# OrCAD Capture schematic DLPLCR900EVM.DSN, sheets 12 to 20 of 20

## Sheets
12 P09-Controller USB Osc Rst SSP: size A3
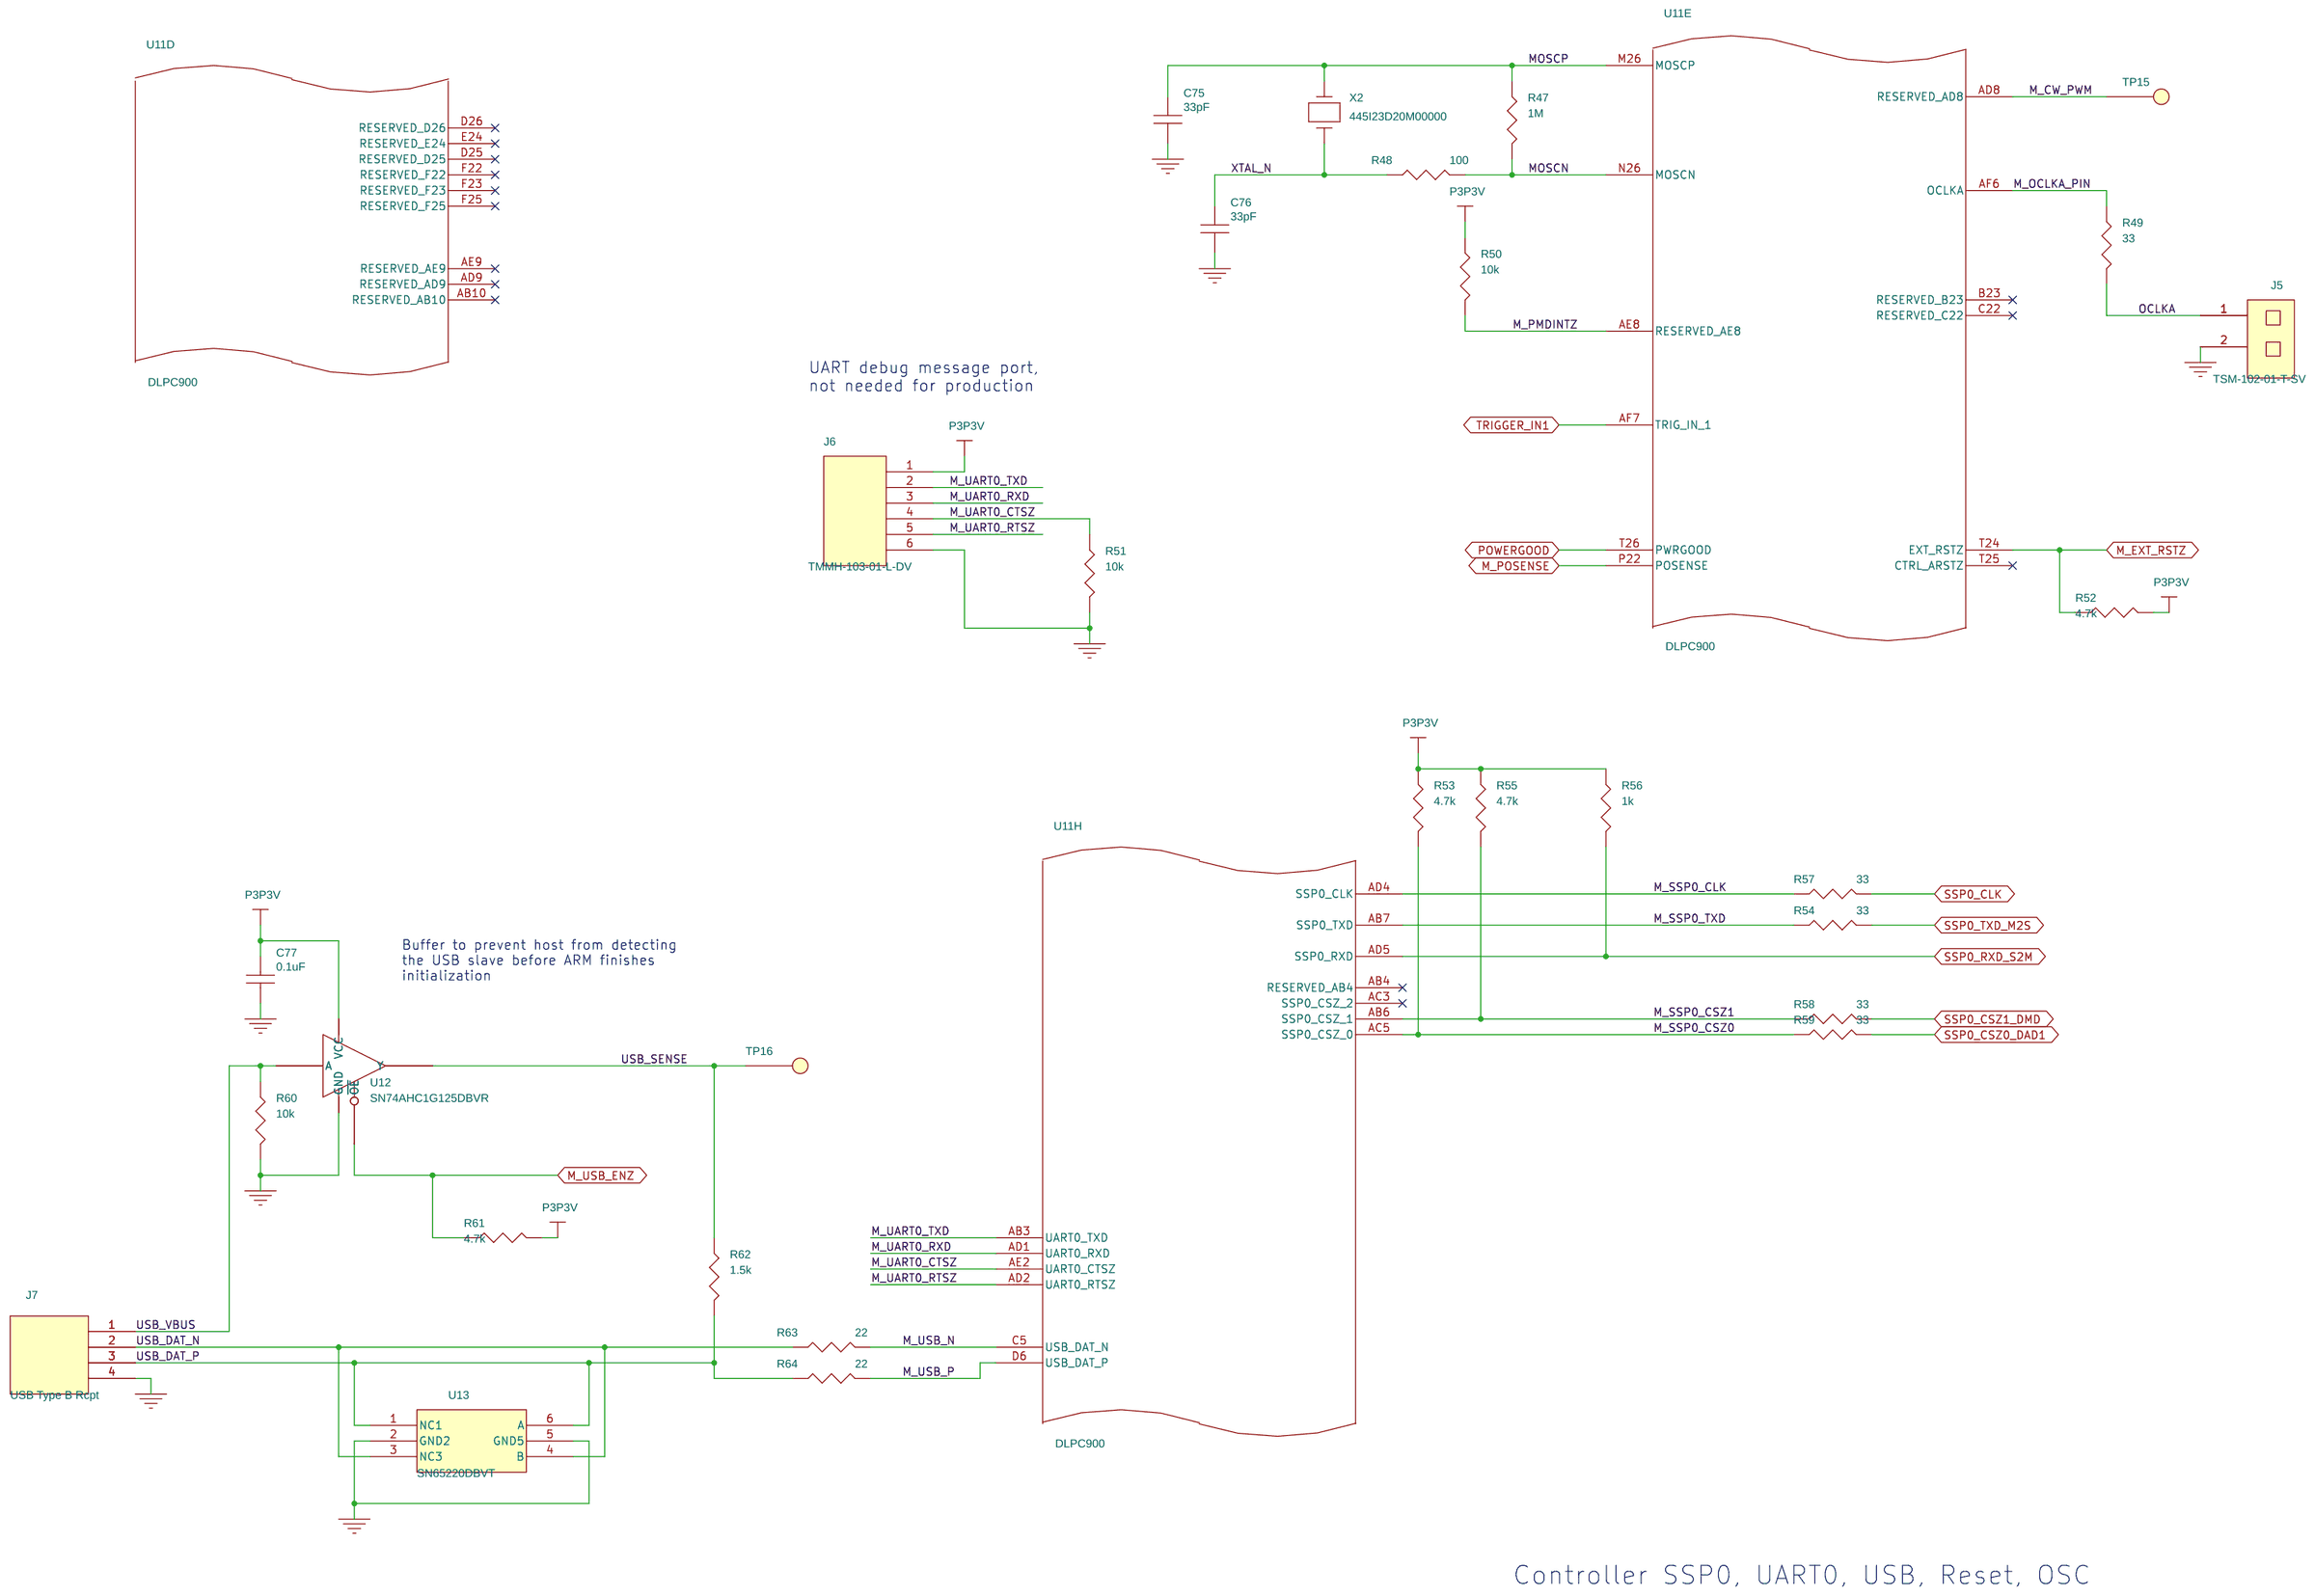
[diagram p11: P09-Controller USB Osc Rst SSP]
13 P08-Controller Vid DMD DAD io: size A3
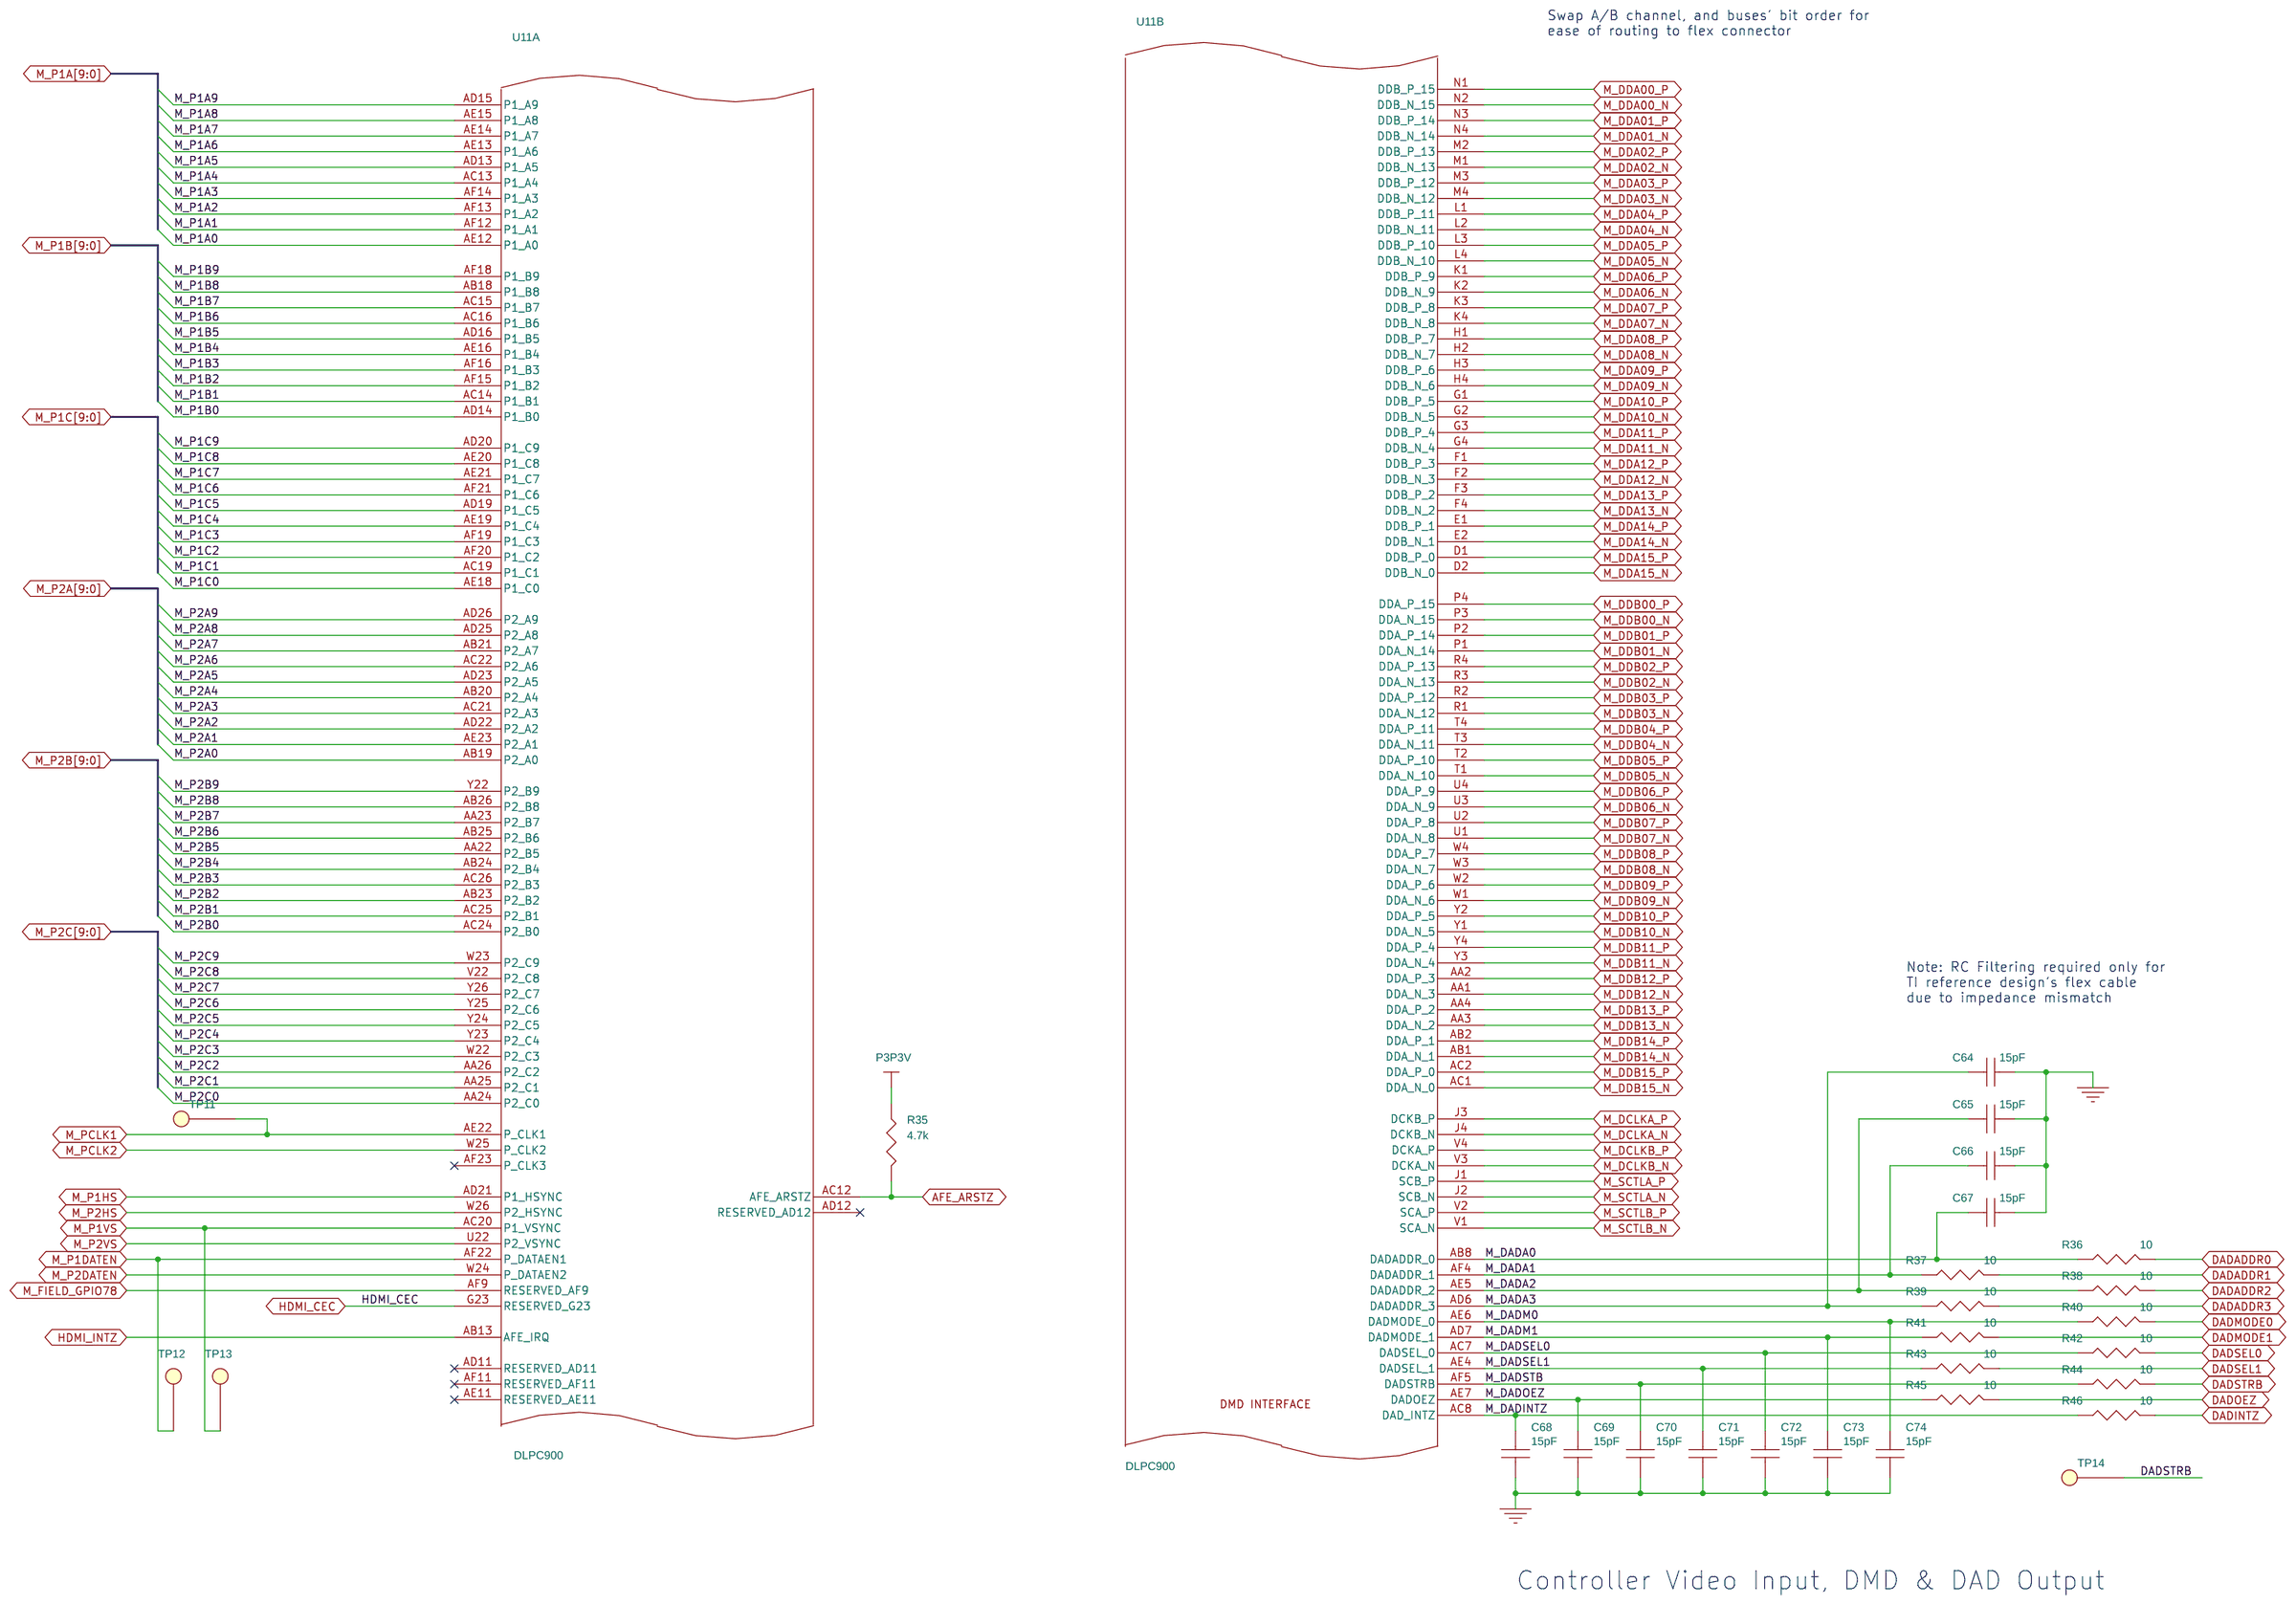
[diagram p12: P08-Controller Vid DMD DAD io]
14 P01-Title
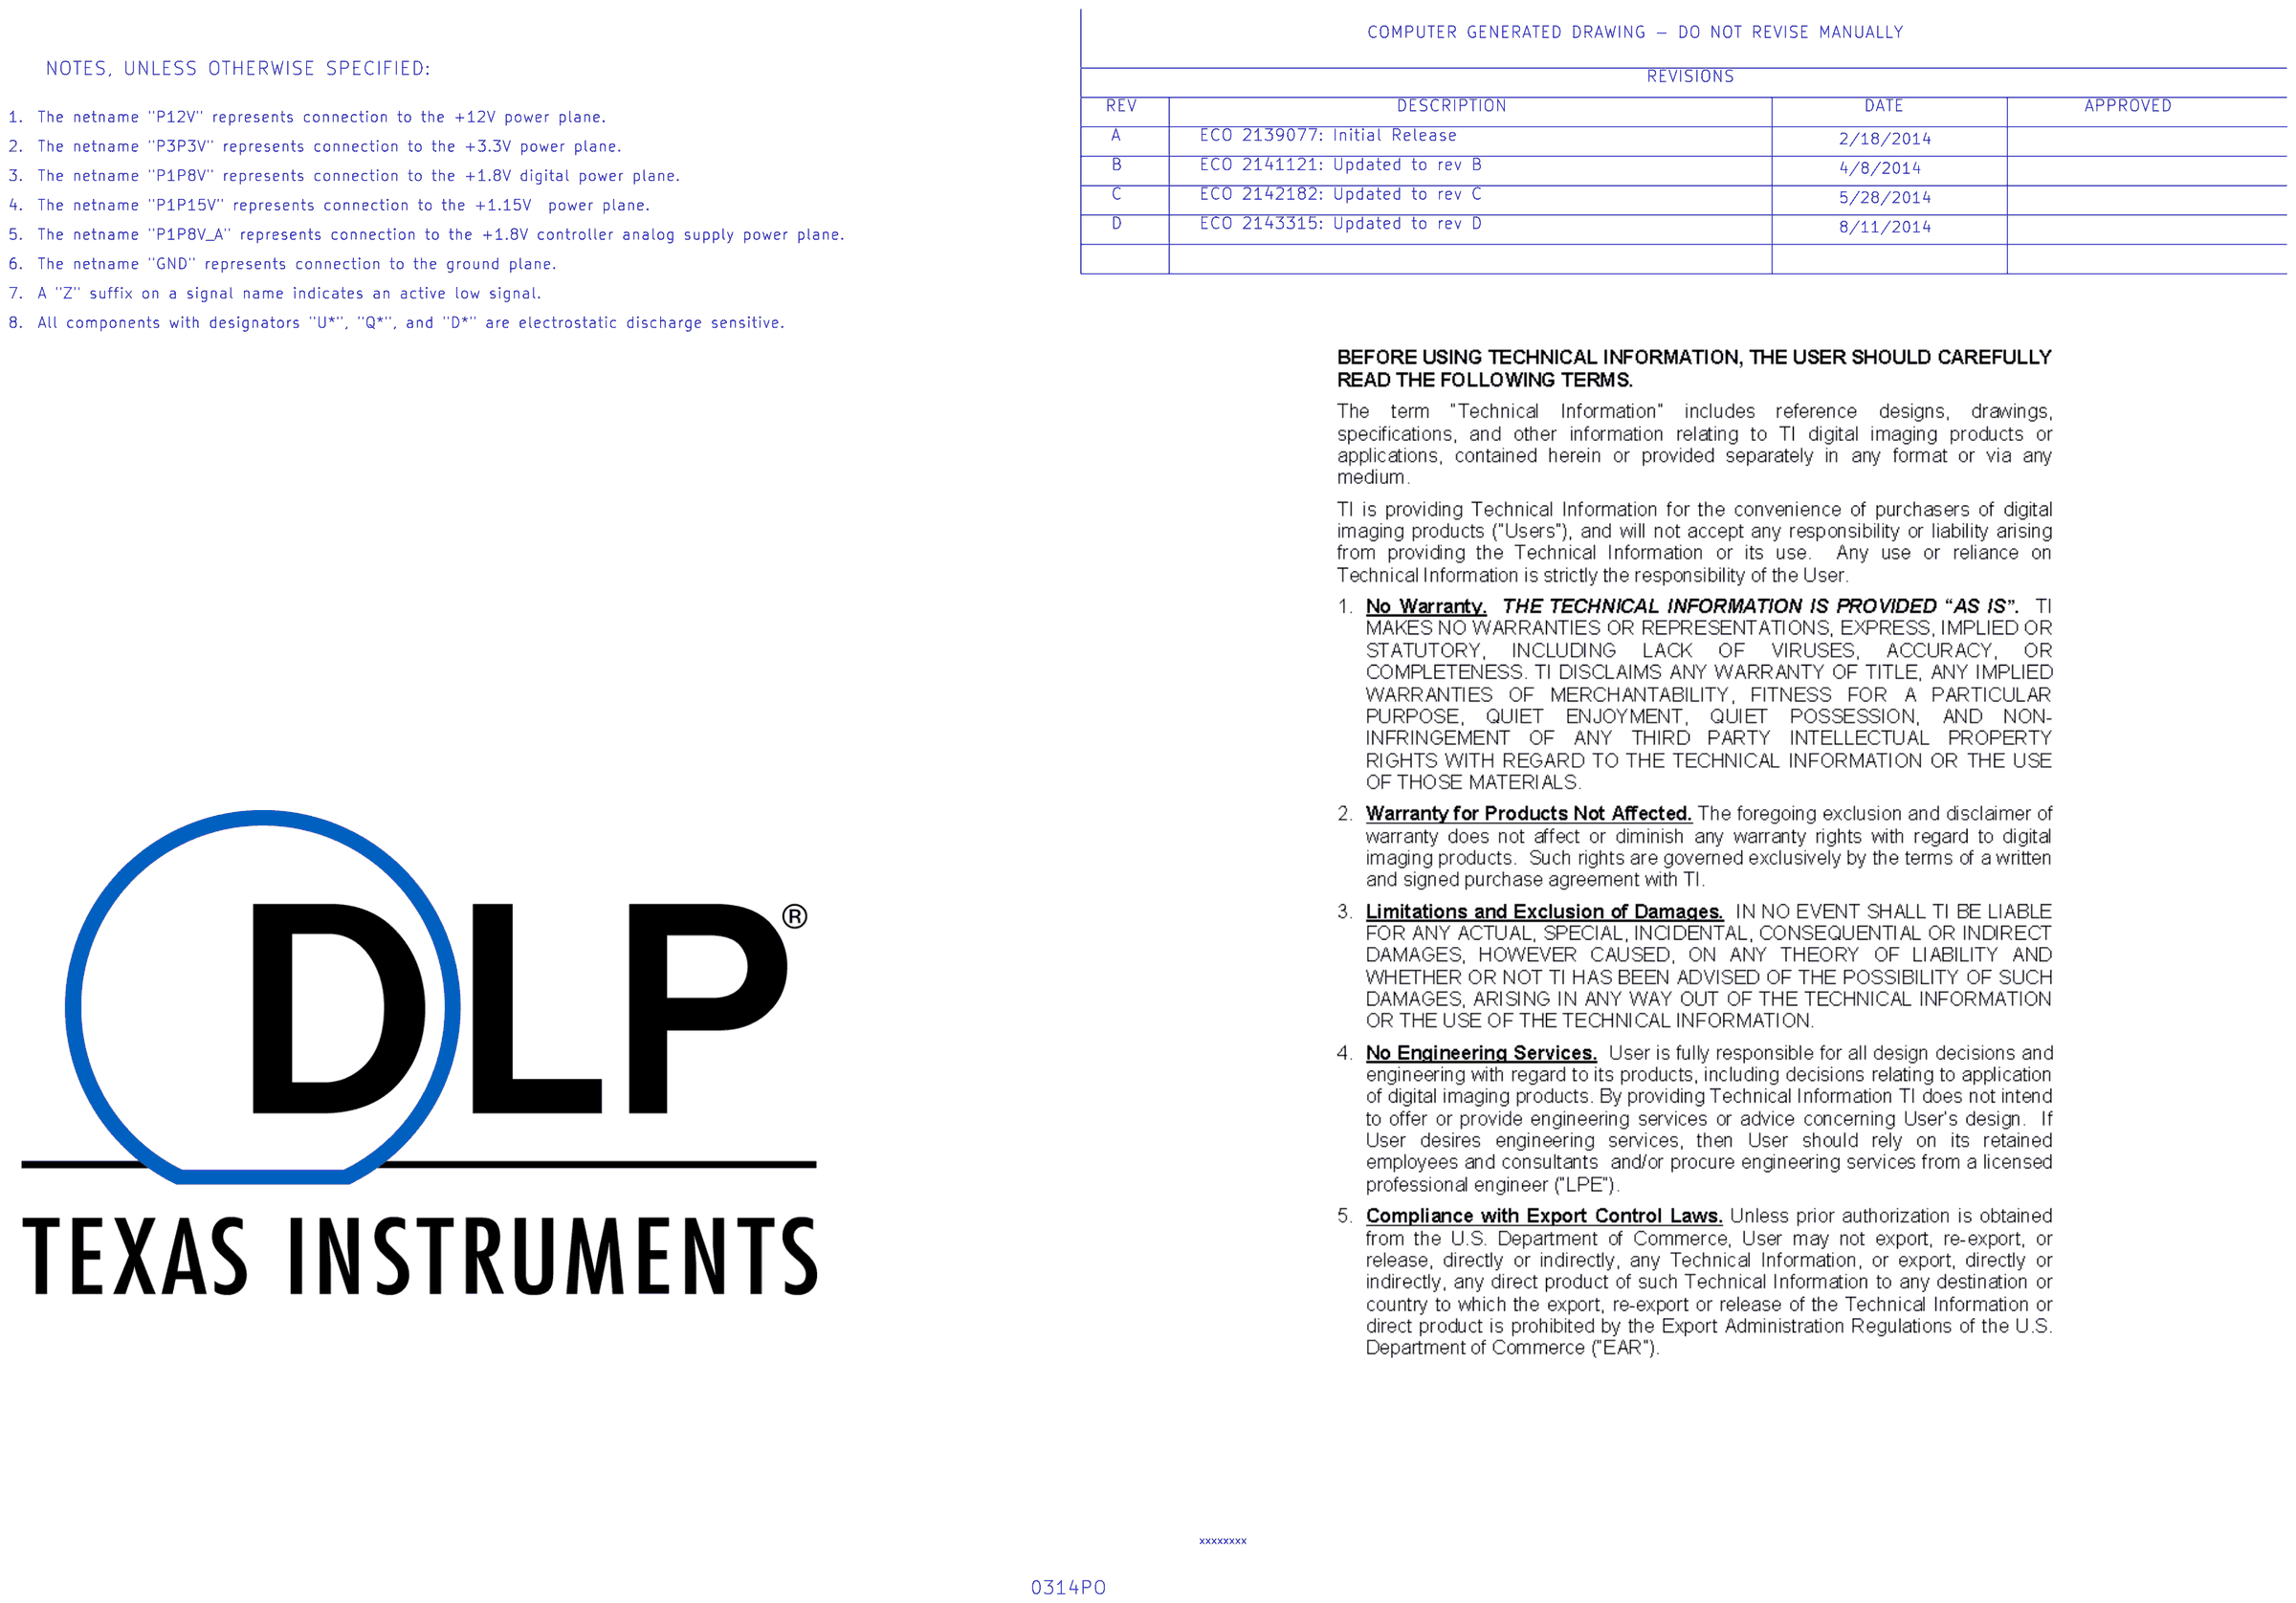
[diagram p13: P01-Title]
15 P03-Table Of Contents
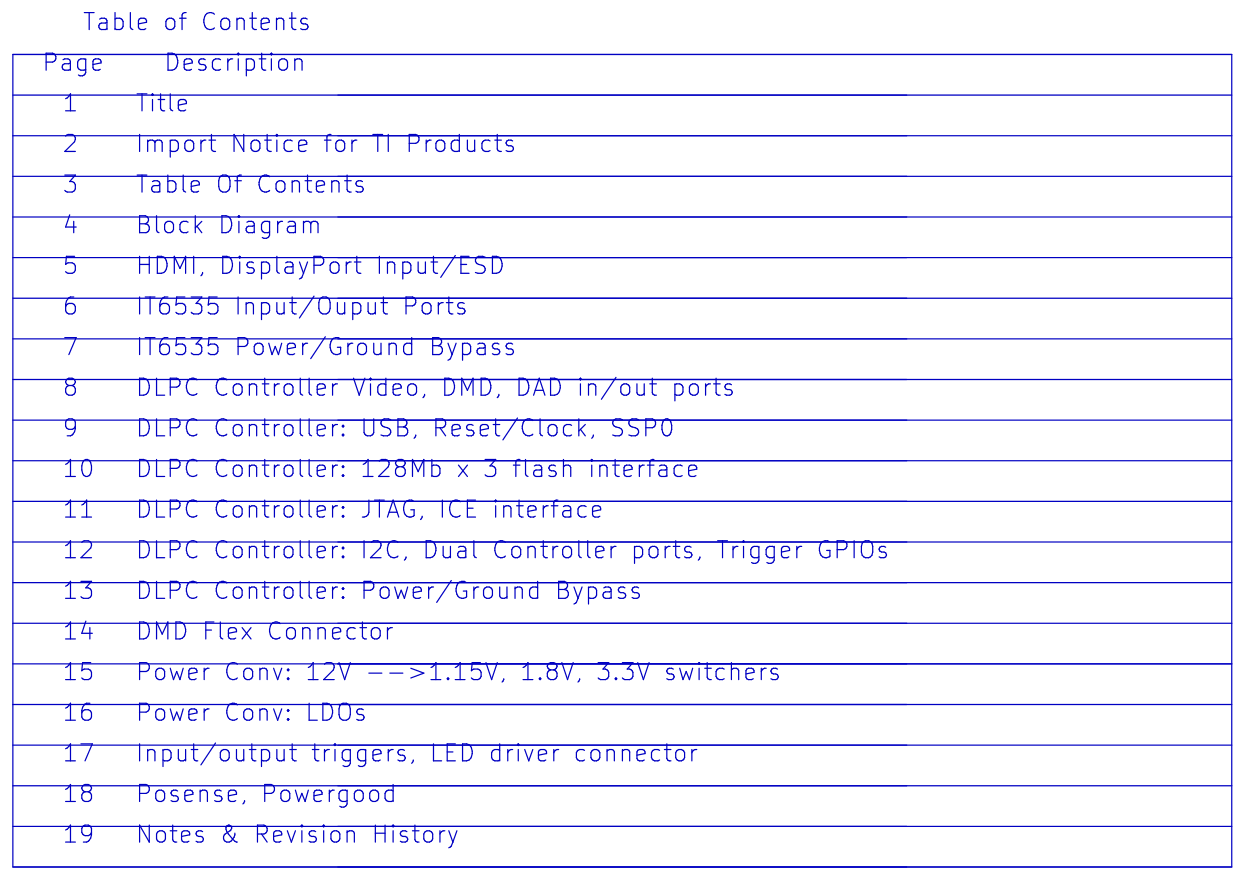
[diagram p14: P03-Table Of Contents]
16 P04-Block Diagram
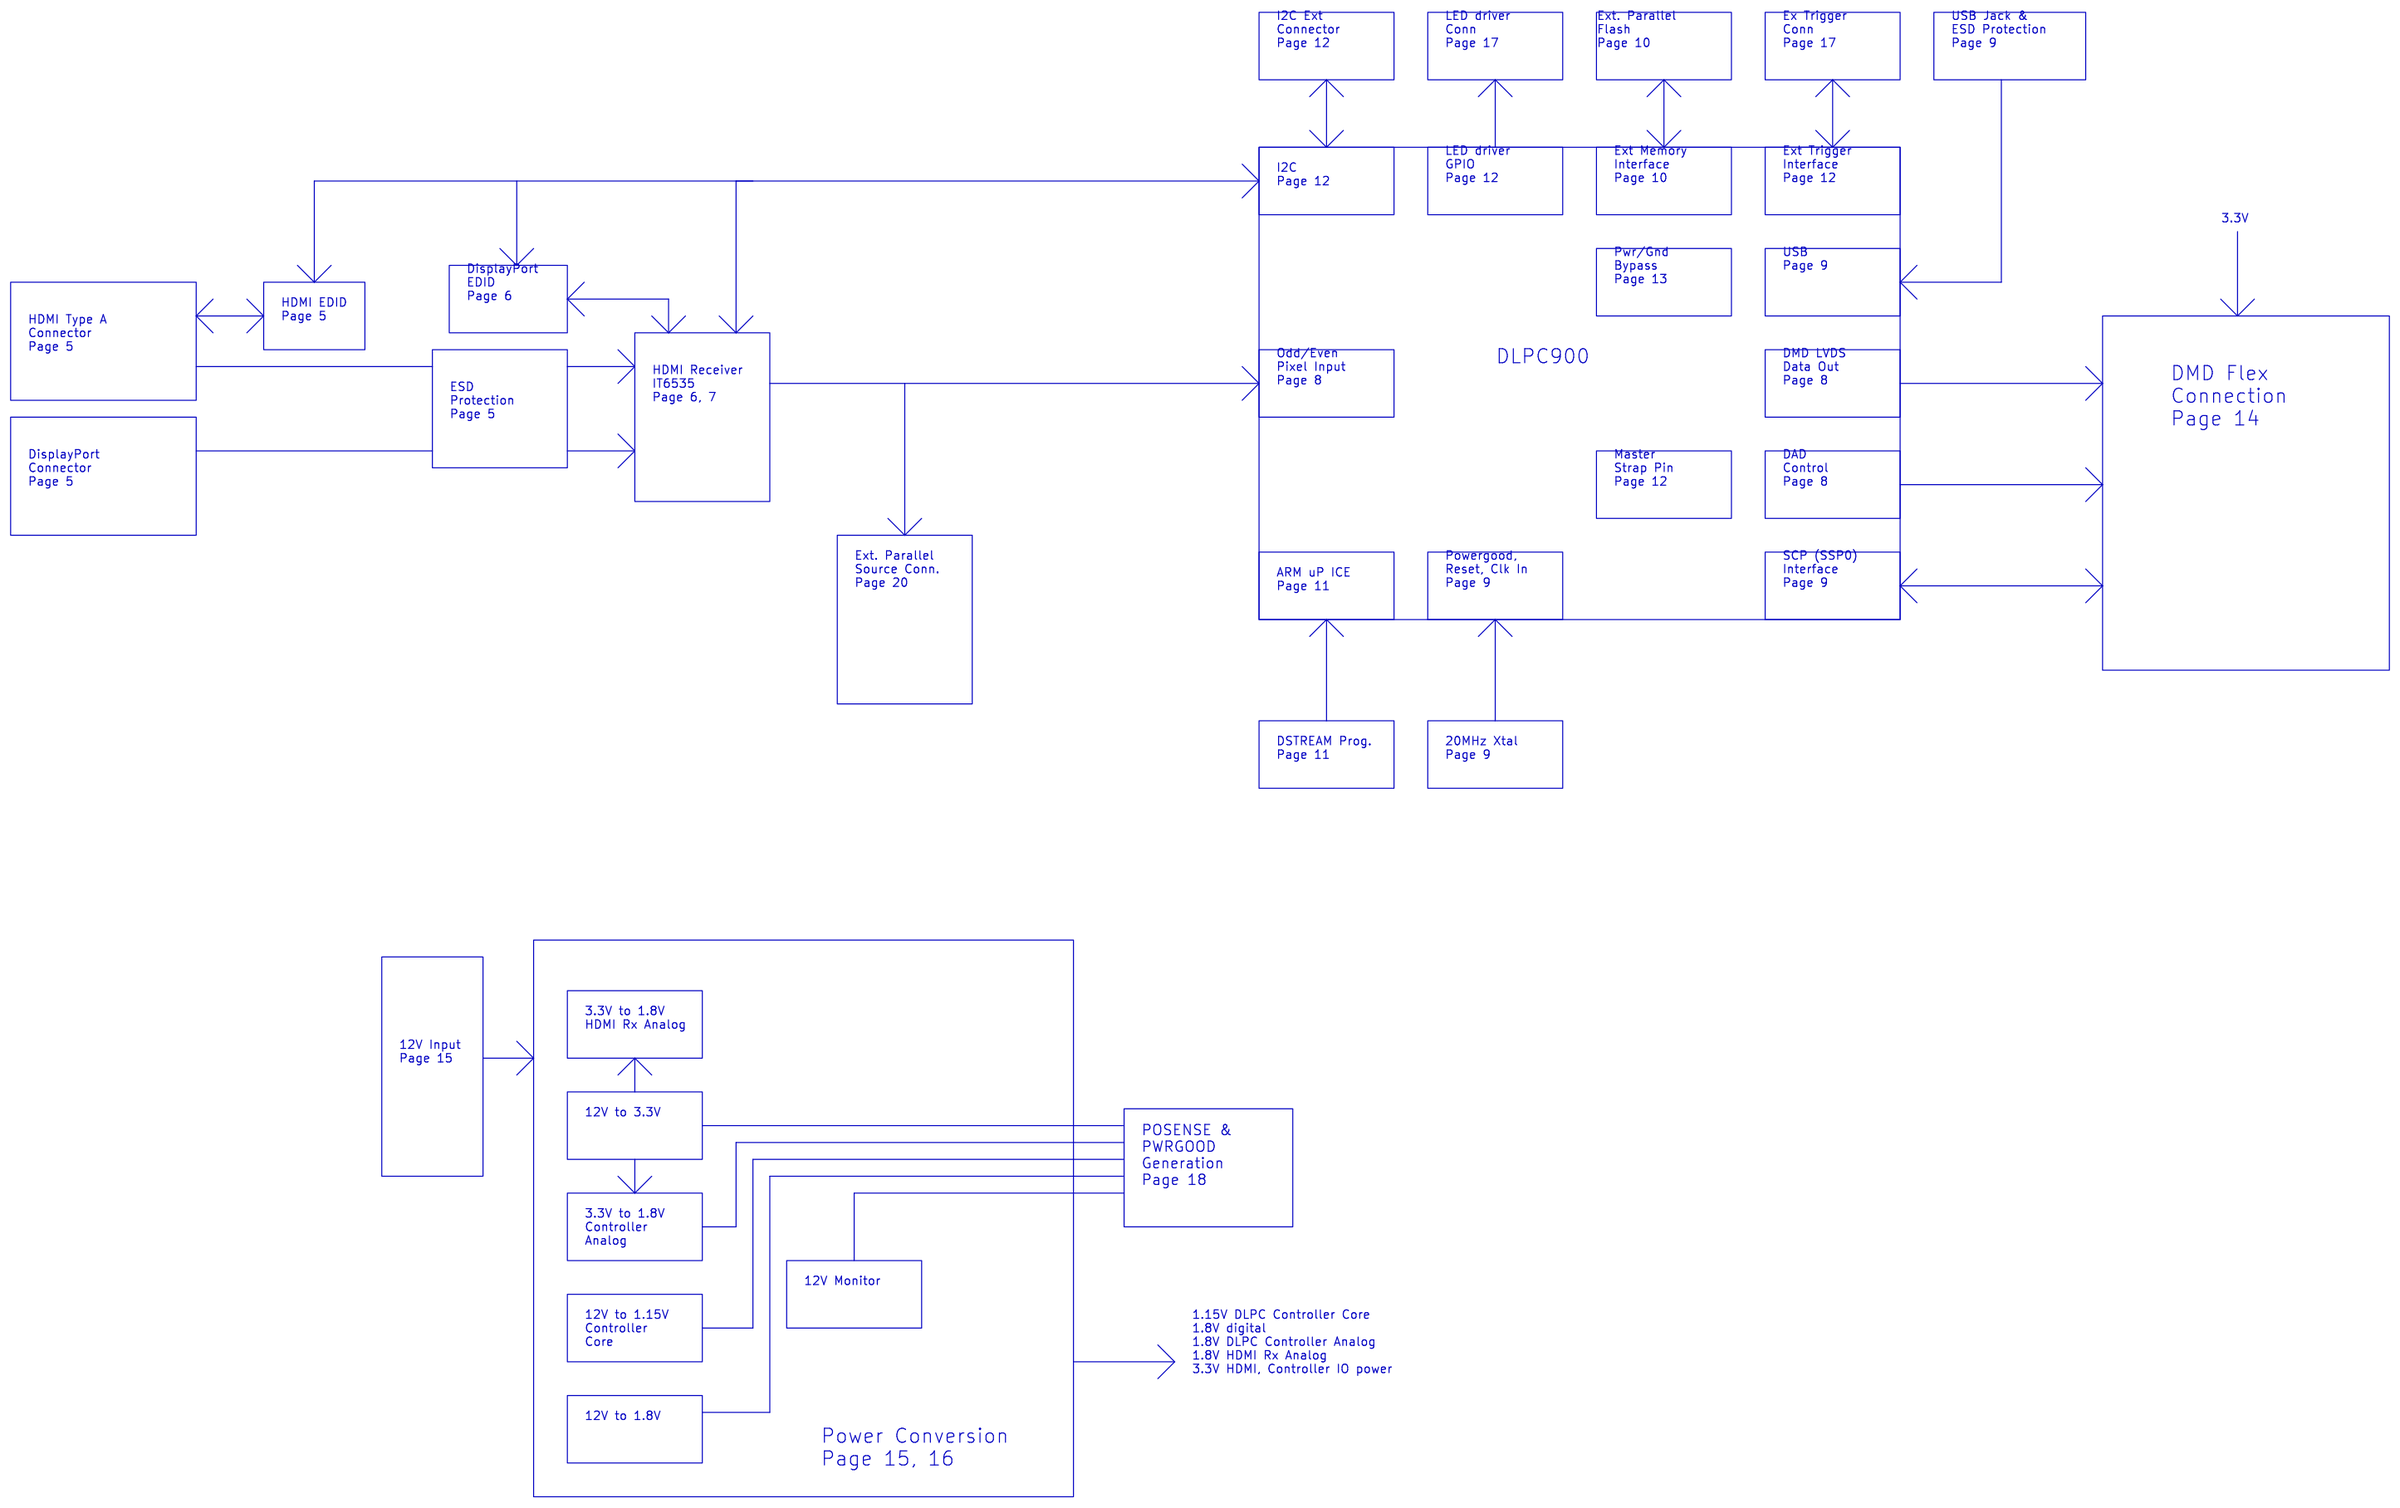
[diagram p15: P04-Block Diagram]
17 P06-IT6535 Input Output Ports: size A3
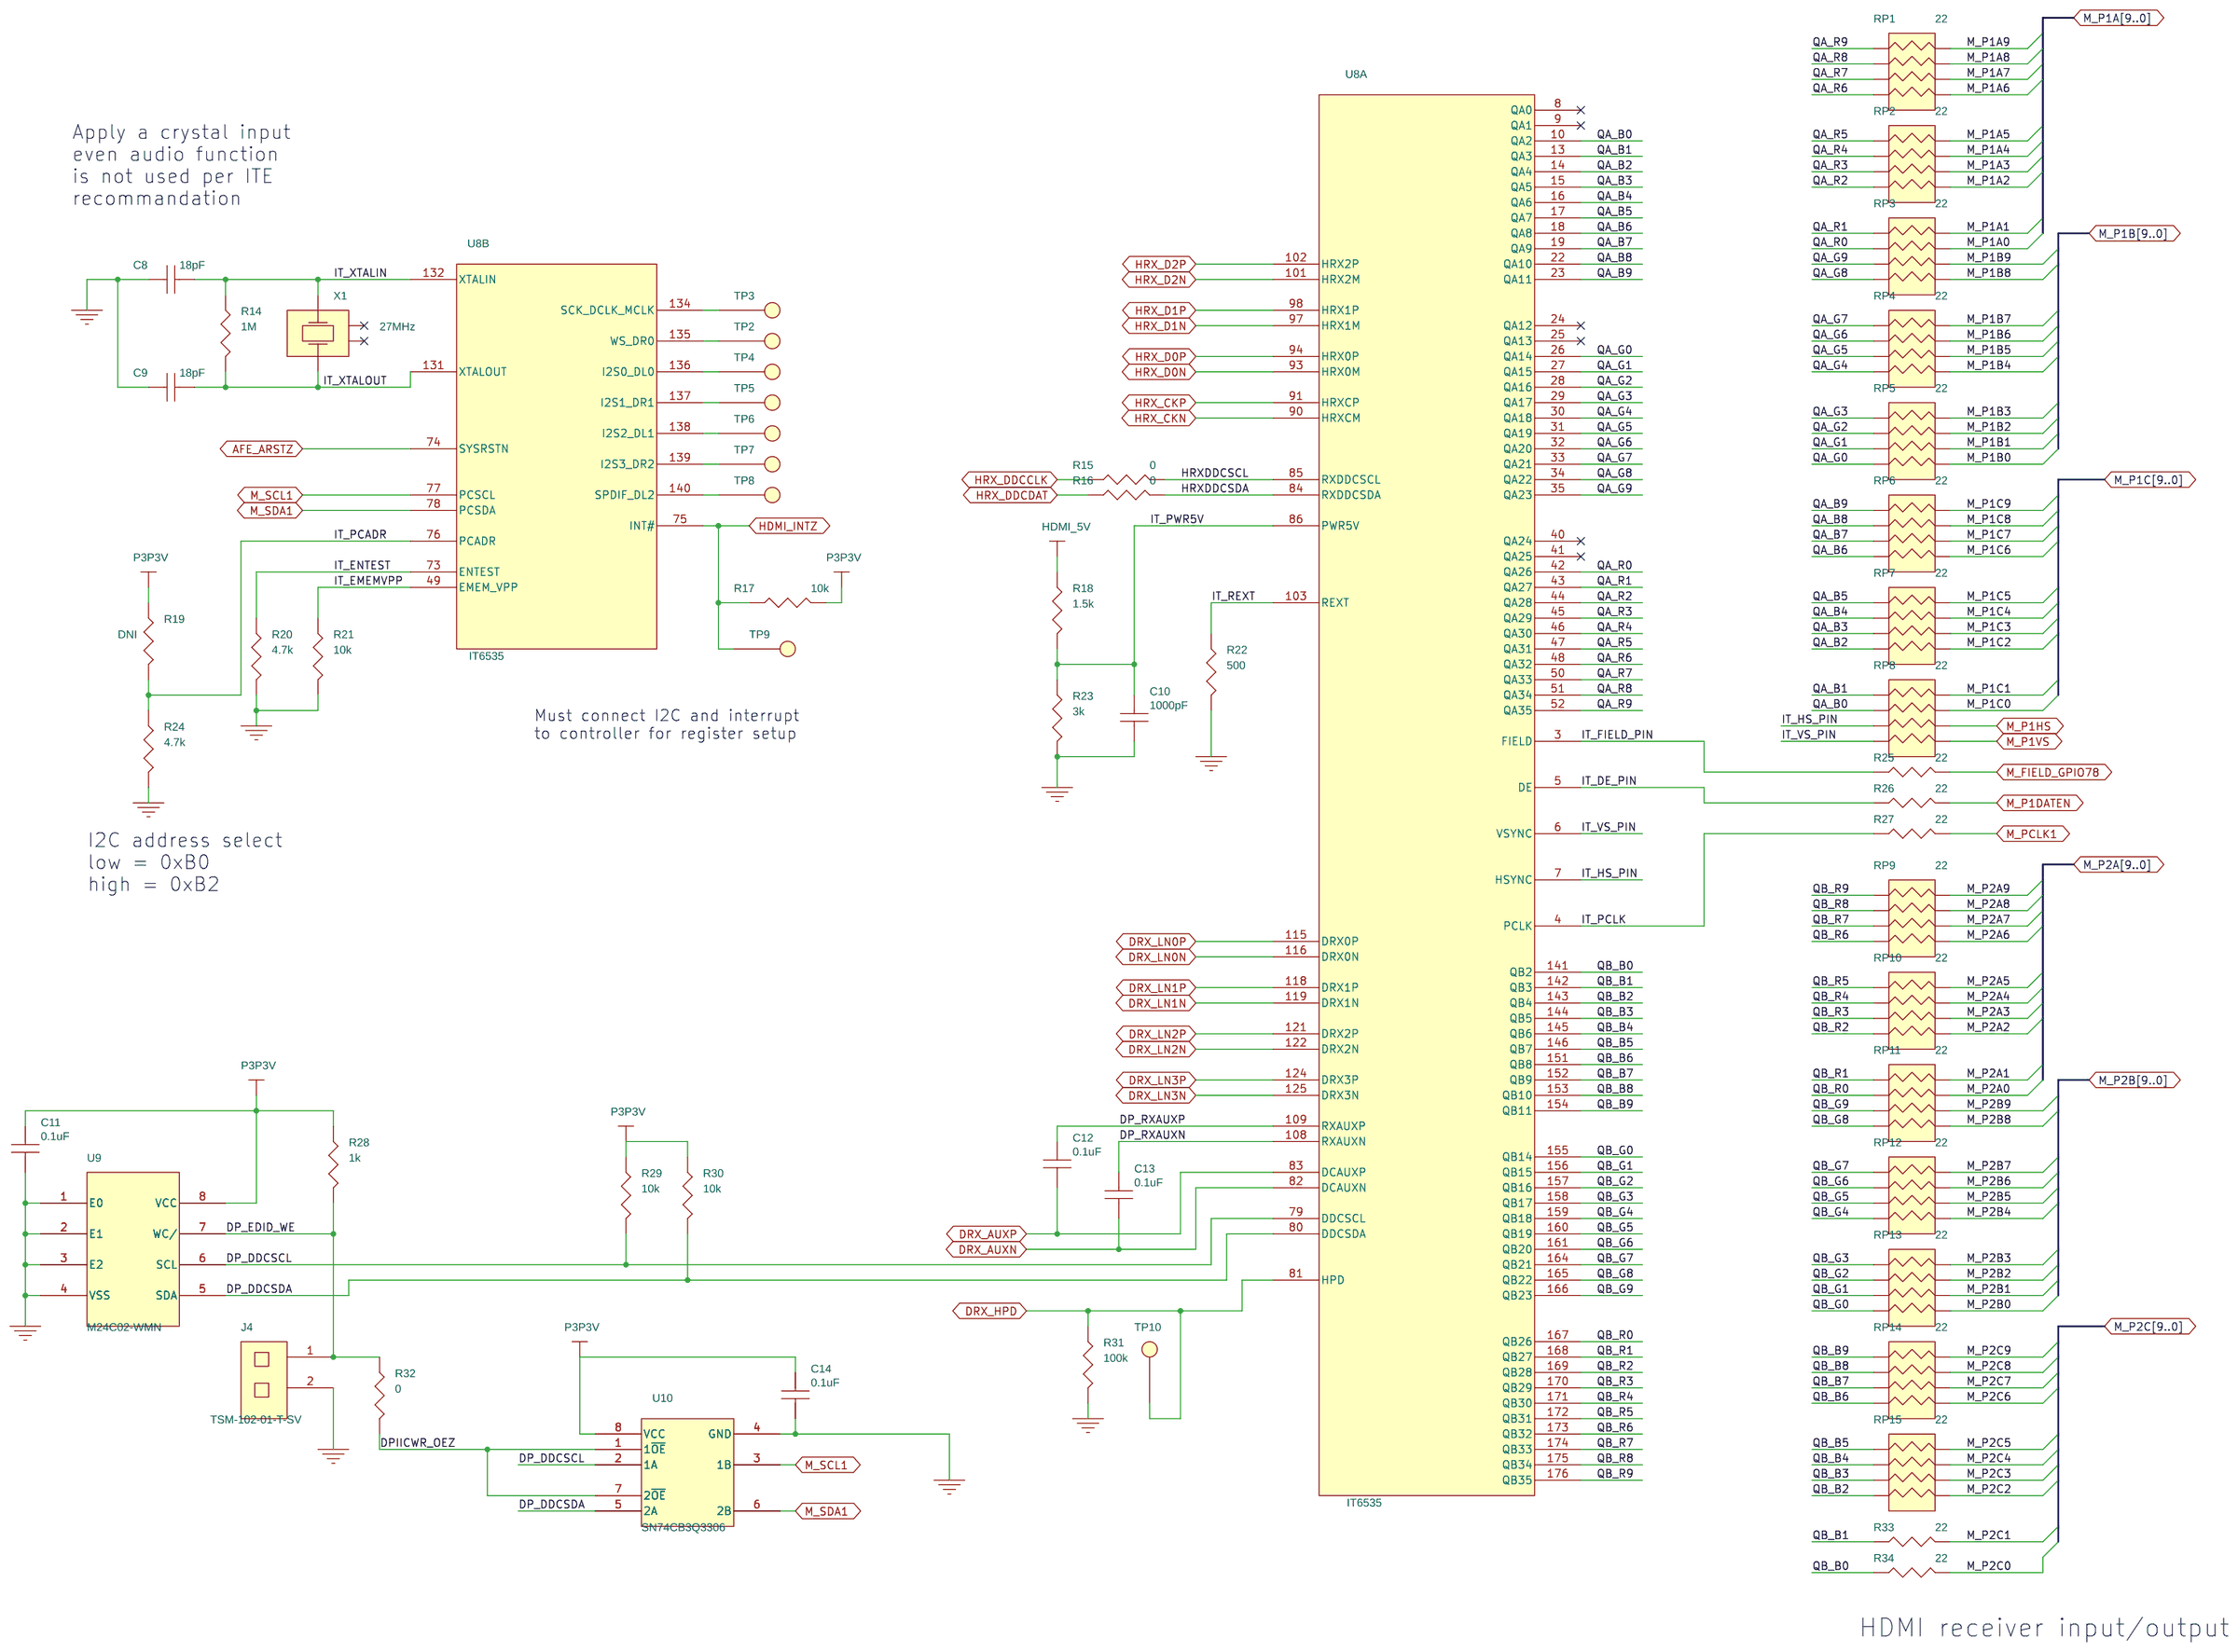
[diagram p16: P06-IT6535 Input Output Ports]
18 P13-Controller Pwr/Gnd: size A3
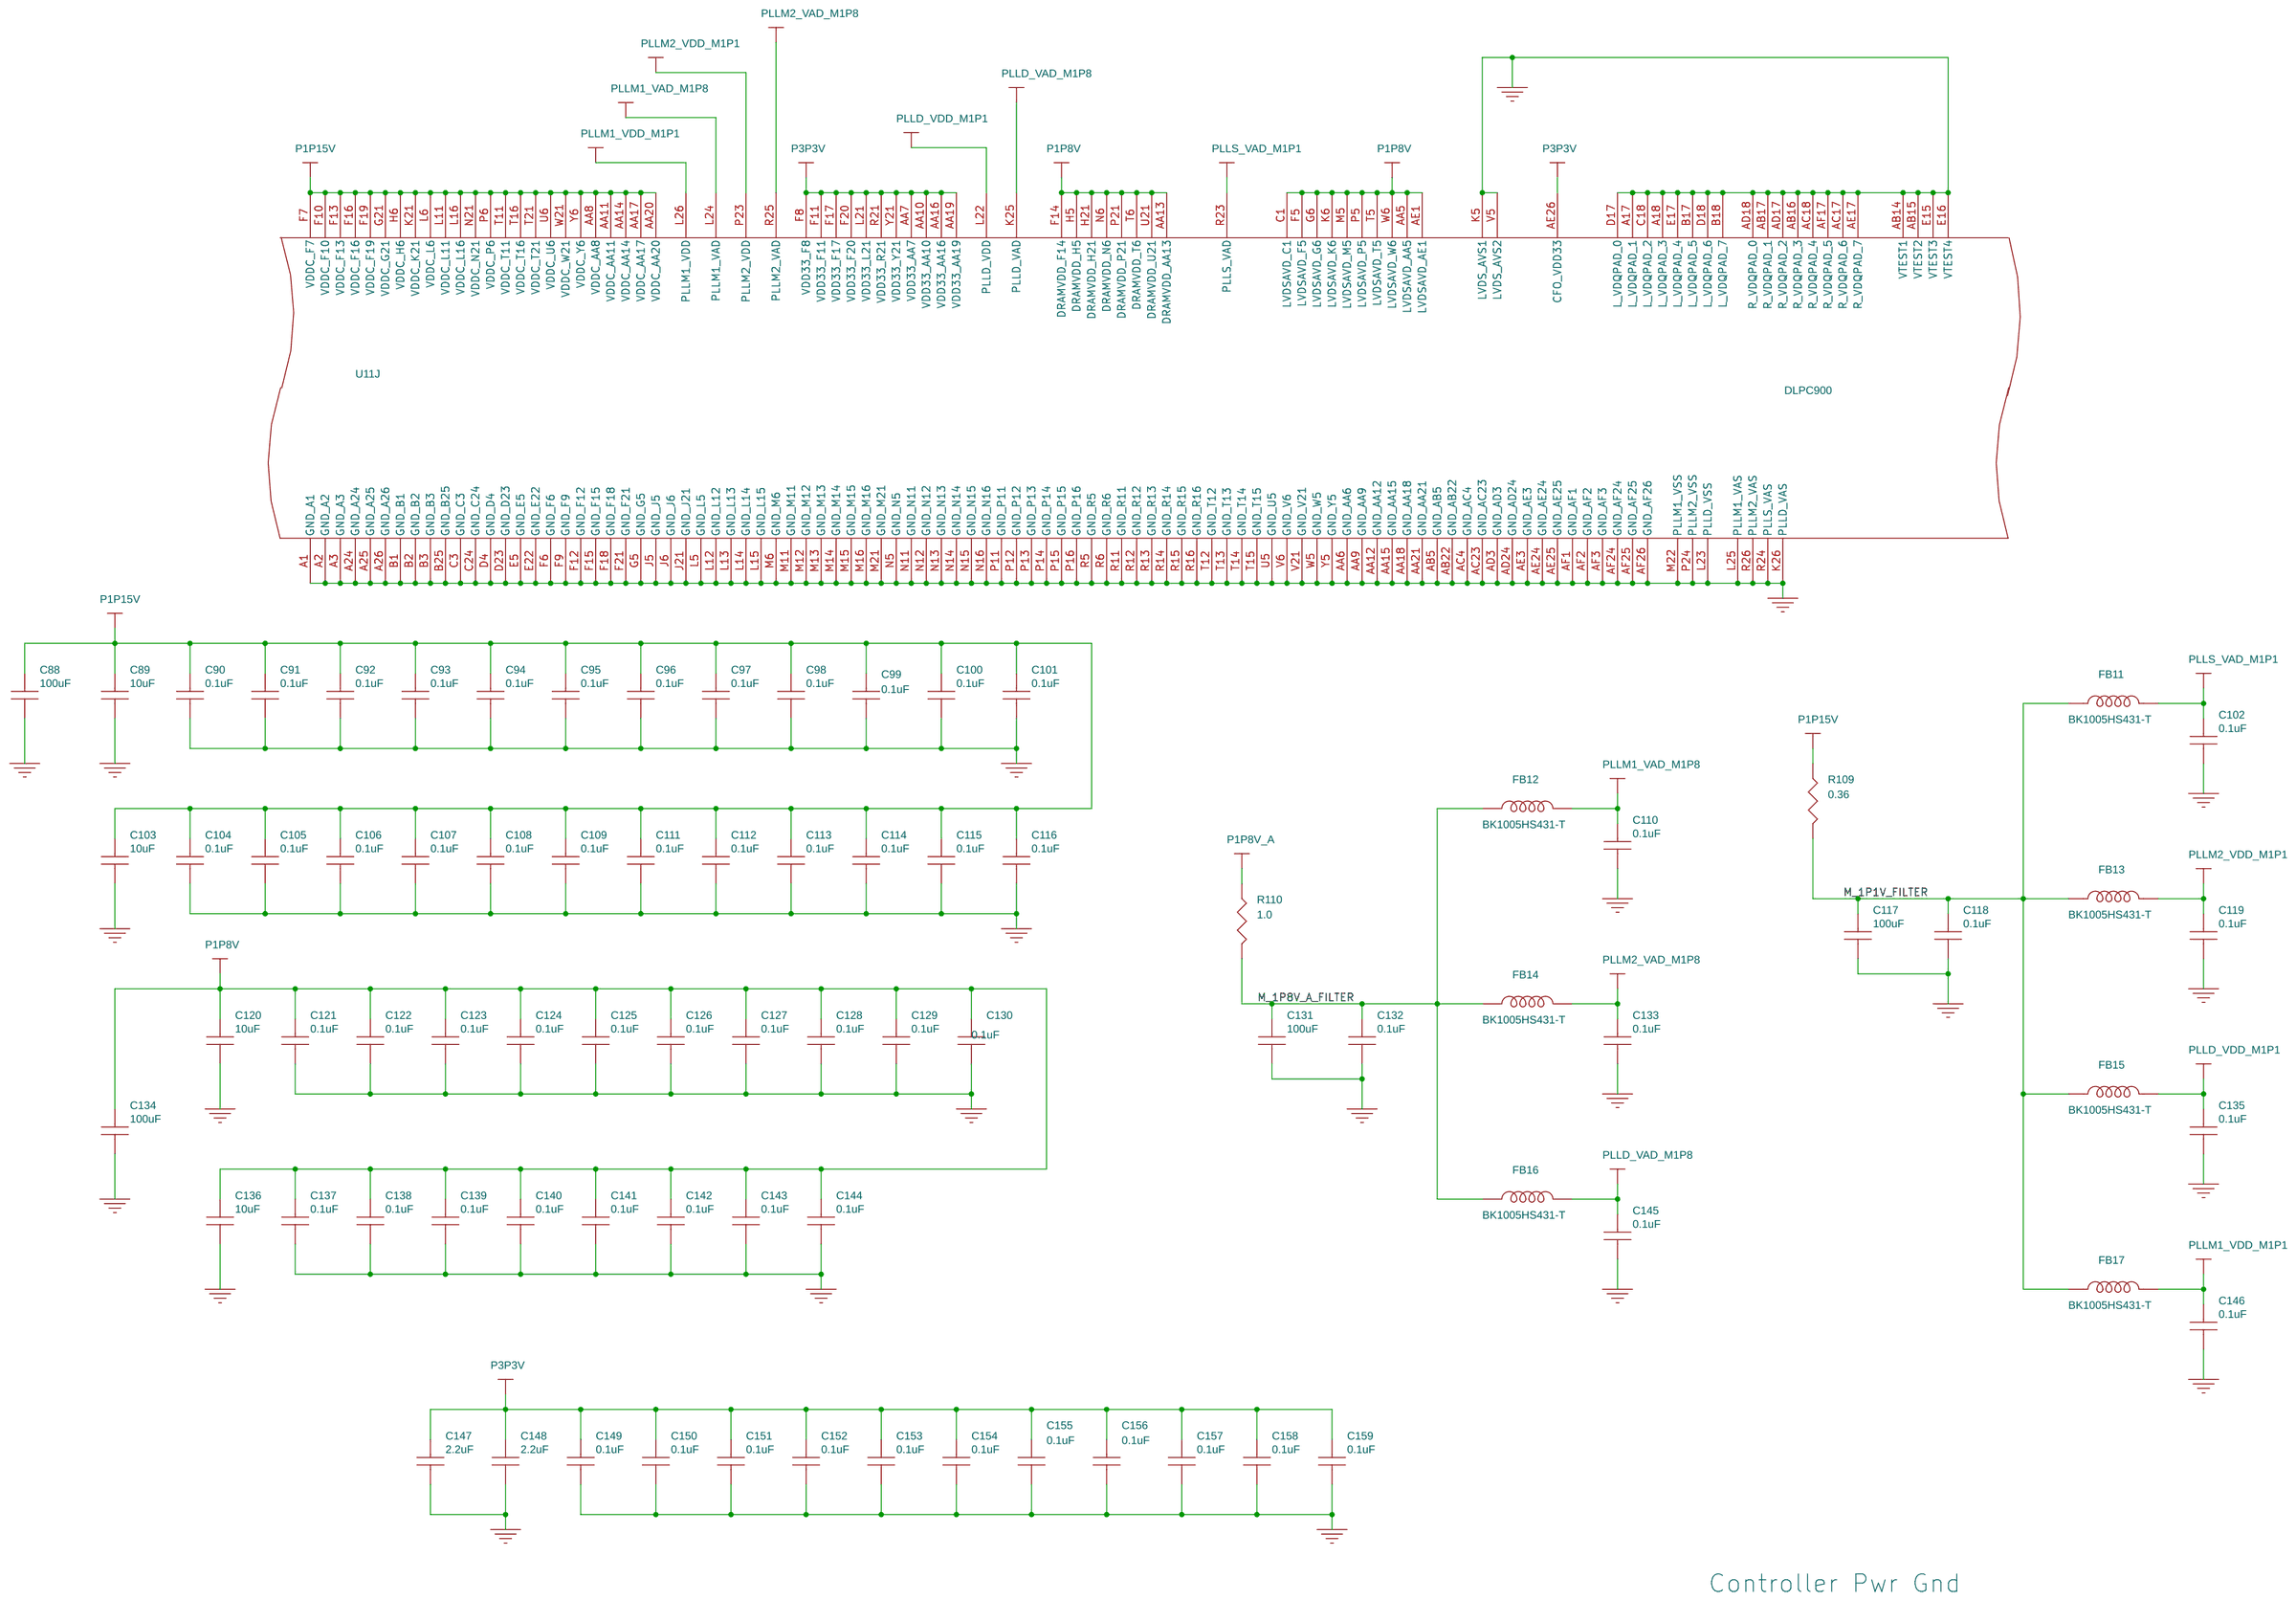
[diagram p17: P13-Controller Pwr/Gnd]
19 P07-IT6535 Pwr/Gnd: size A3
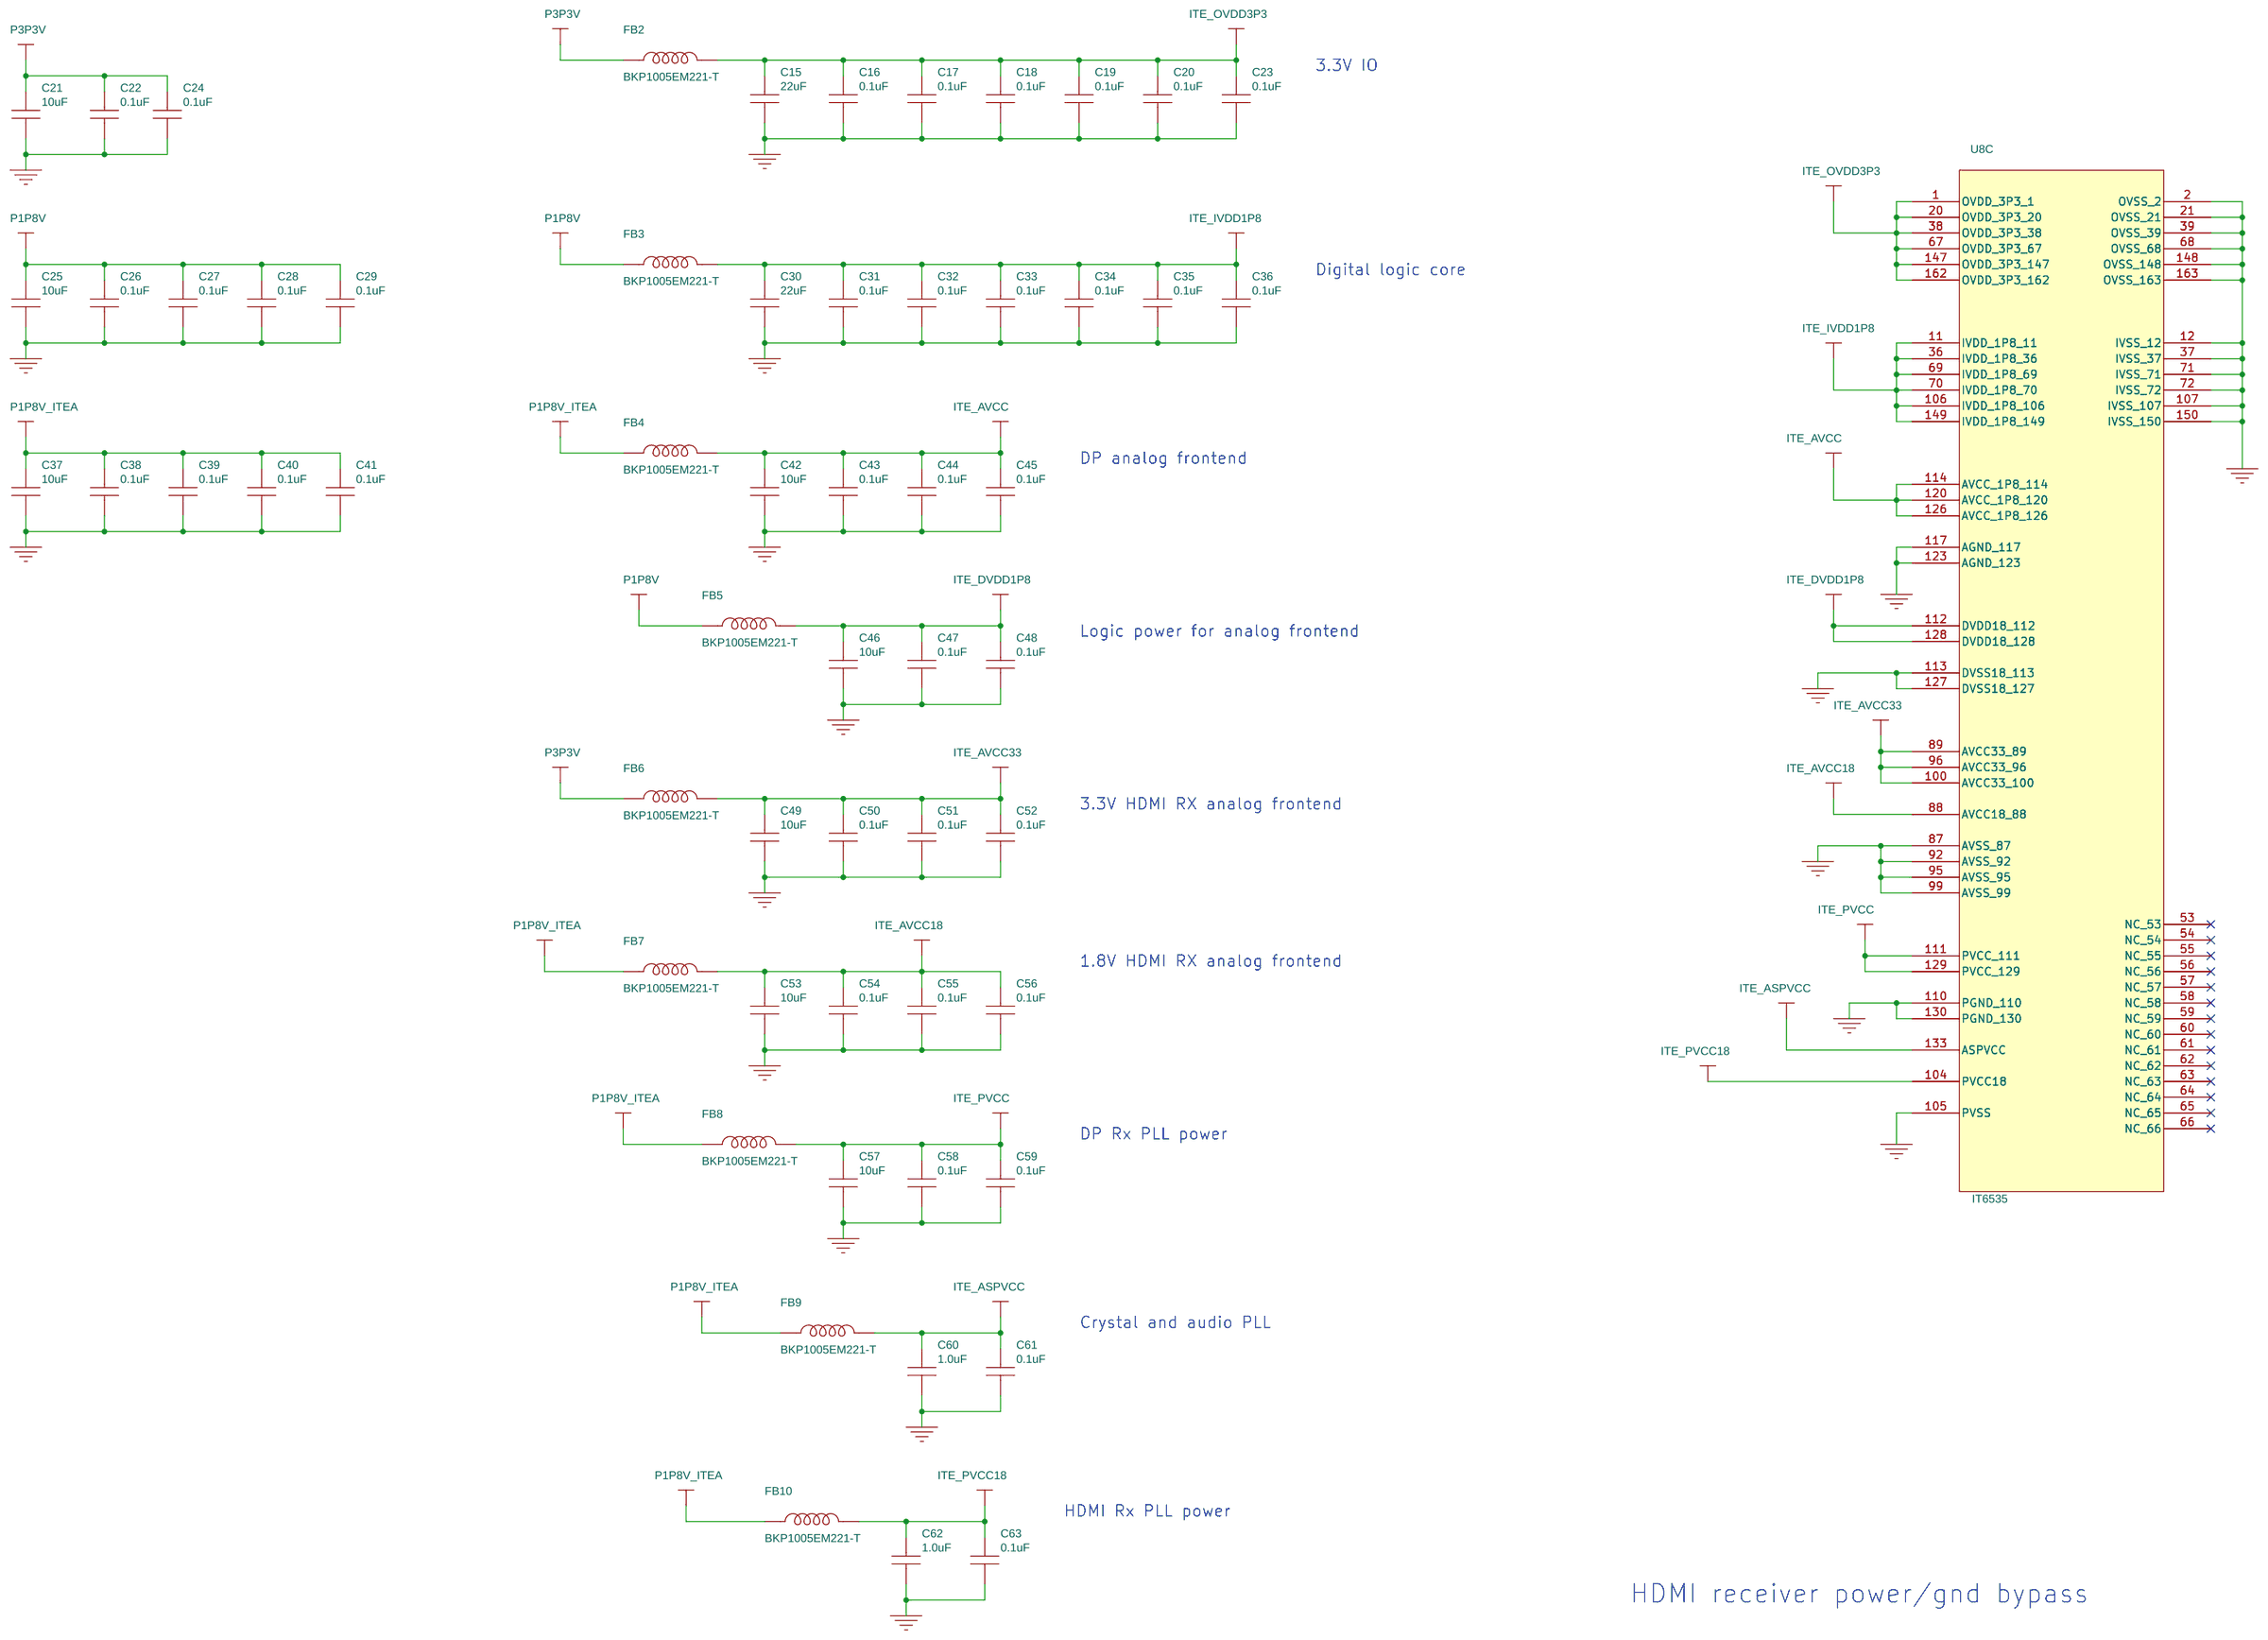
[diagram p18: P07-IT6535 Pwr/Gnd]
20 P05-HDMI/DP Conn, ESD: size A3
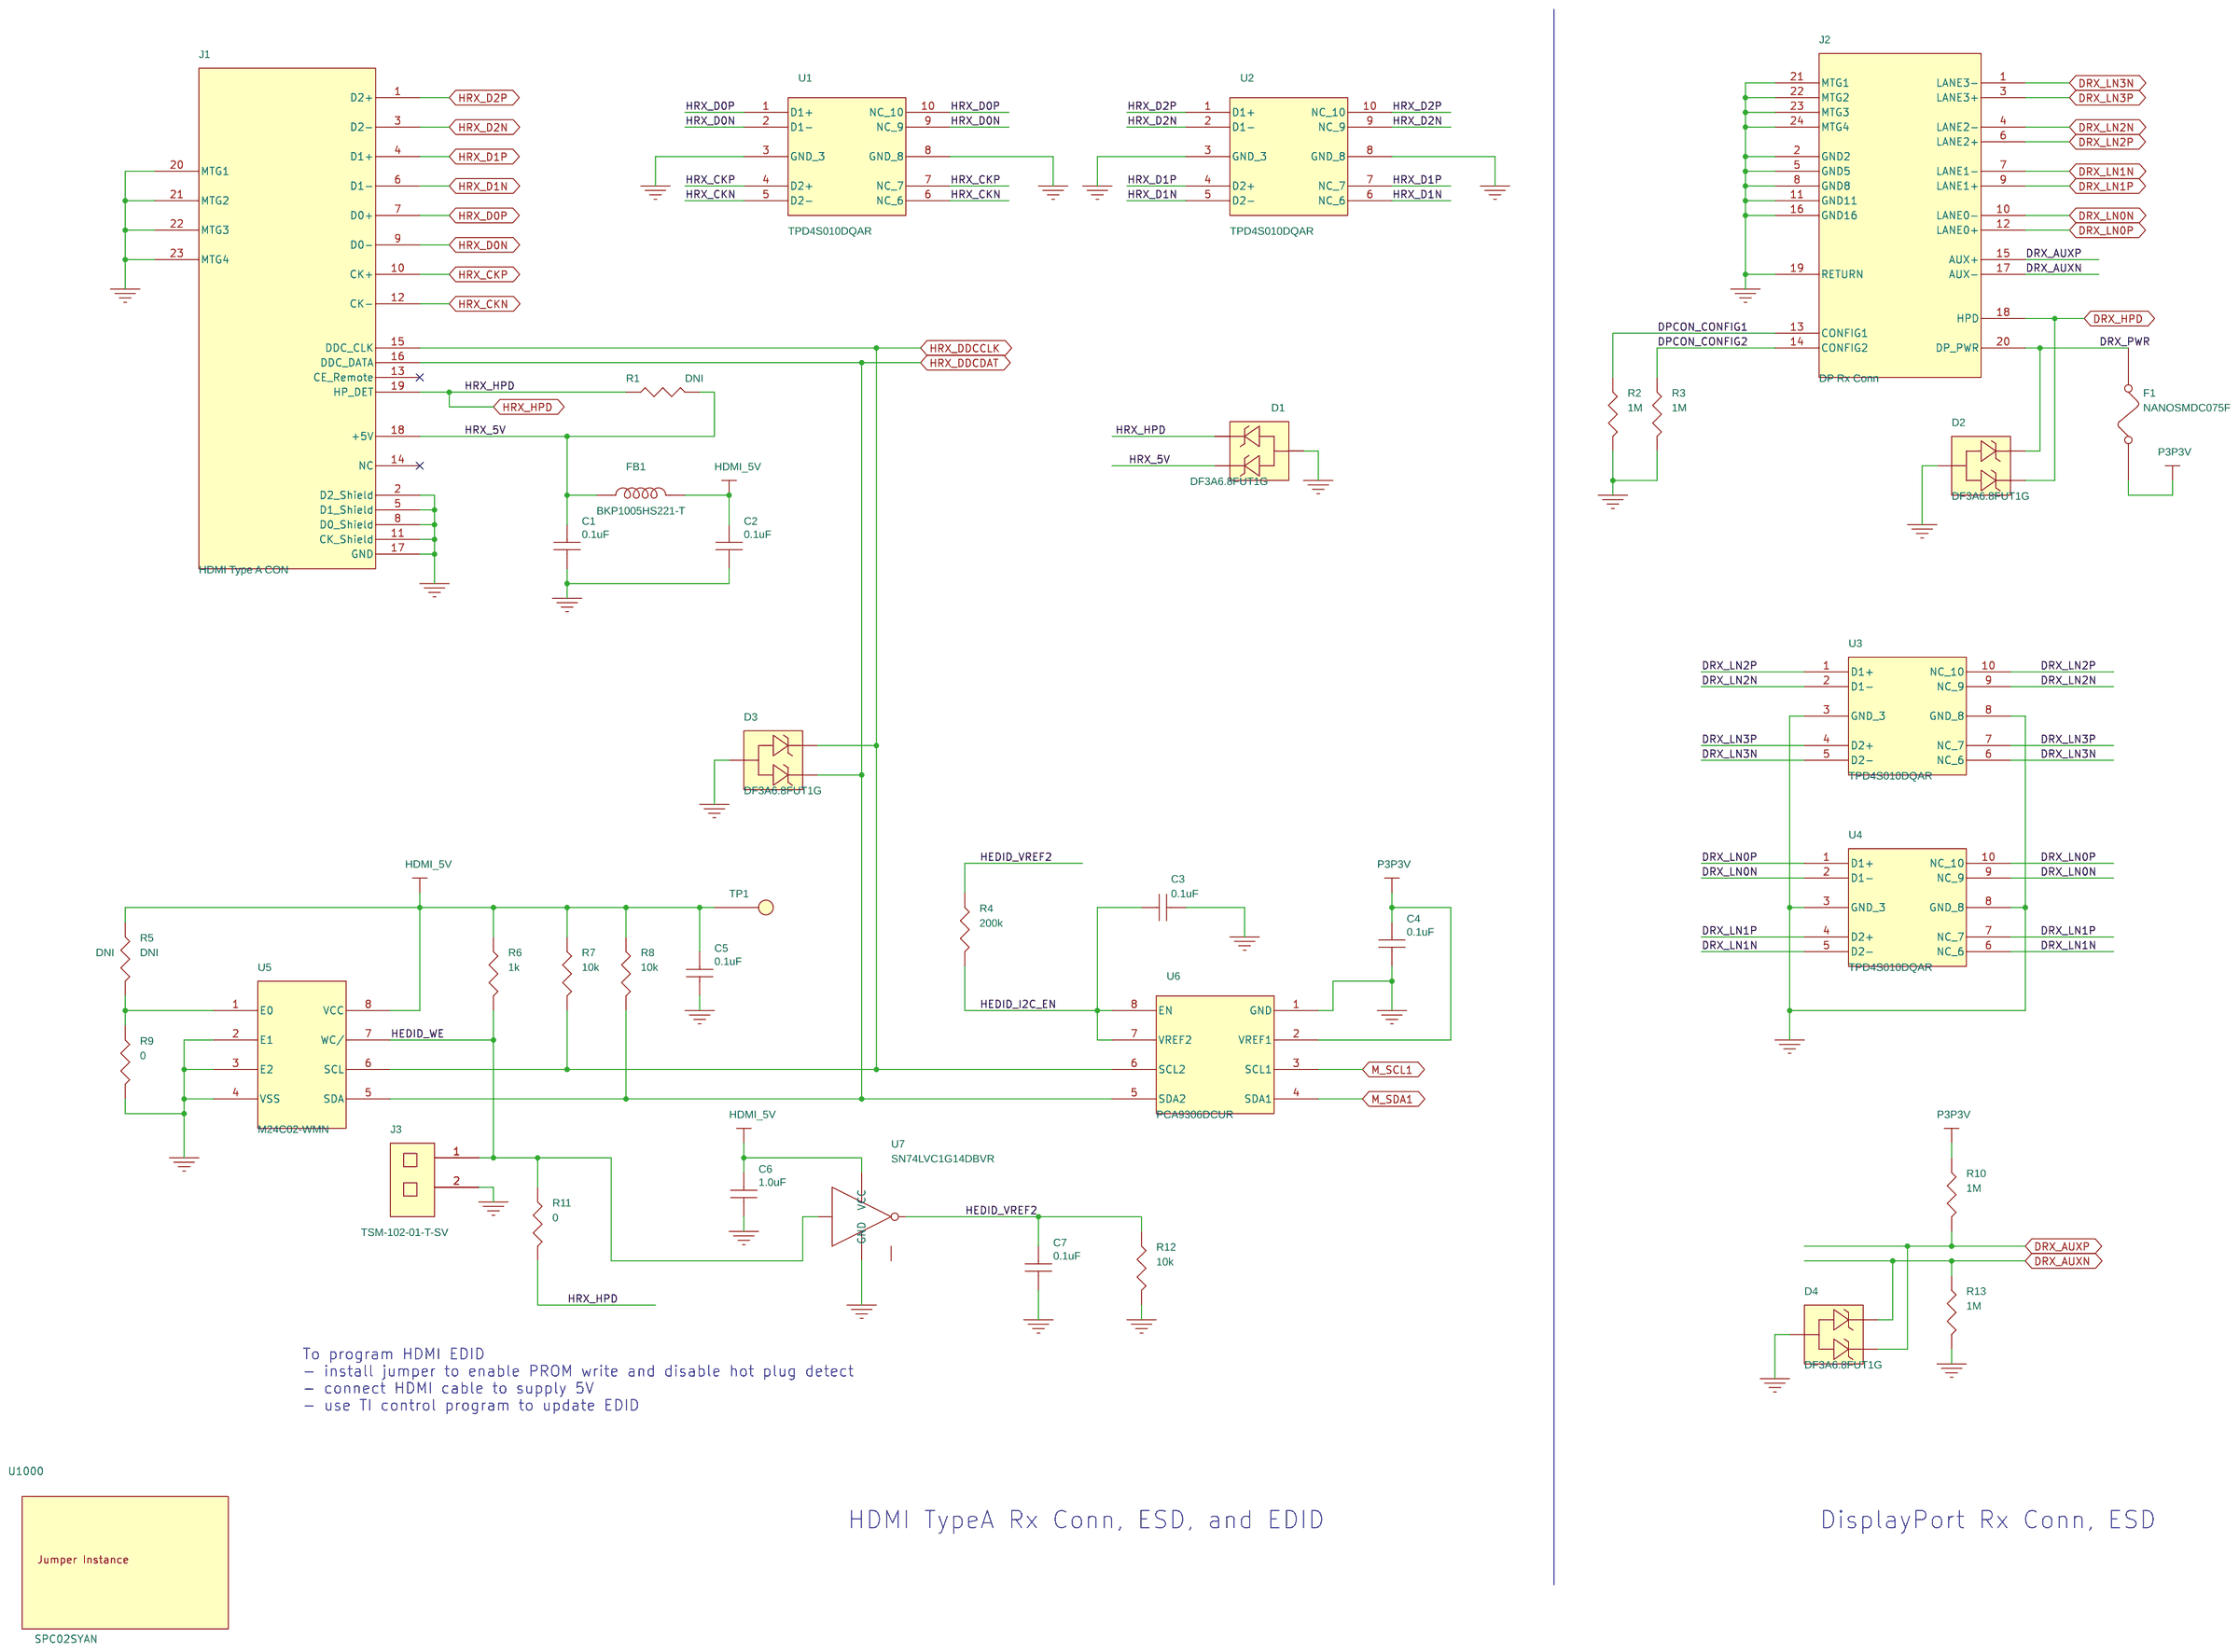
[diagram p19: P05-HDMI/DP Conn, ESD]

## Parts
sheet P05-HDMI/DP Conn, ESD
C1  0.1uF  [0402]
C2  0.1uF  [0402]
C3  0.1uF  [0402]
C4  0.1uF  [0402]
C5  0.1uF  [0402]
C6  1.0uF  [0402]
C7  0.1uF  [0402]
D1  DF3A6.8FUT1G  [SOT-323_SC70_ONSEMI_MOD]
D2  DF3A6.8FUT1G  [SOT-323_SC70_ONSEMI_MOD]
D3  DF3A6.8FUT1G  [SOT-323_SC70_ONSEMI_MOD]
D4  DF3A6.8FUT1G  [SOT-323_SC70_ONSEMI_MOD]
F1  NANOSMDC075F  [1206]
FB1  BKP1005HS221-T  [0402]
J1  HDMI Type A CON  [CONN19-HDMI-10029449_FCI_MOD]
J2  DP Rx Conn  [MOLEX_47272-0001_V1]
J3  TSM-102-01-T-SV  [CONN2-SMT-TSM-102-SV_SAMTEC]
R1  DNI  [0402]
R2  1M  [0402]
R3  1M  [0402]
R4  200k  [0402]
R5  DNI  [0402]
R6  1k  [0402]
R7  10k  [0402]
R8  10k  [0402]
R9  0  [0603]
R10  1M  [0402]
R11  0  [0402]
R12  10k  [0402]
R13  1M  [0402]
TP1  Testpoint  [TP-25RD12]
U1  TPD4S010DQAR  [SOIC10-DQA_TI]
U2  TPD4S010DQAR  [SOIC10-DQA_TI]
U3  TPD4S010DQAR  [SOIC10-DQA_TI]
U4  TPD4S010DQAR  [SOIC10-DQA_TI]
U5  M24C02-WMN  [SOIC8]
U6  PCA9306DCUR  [SOIC8-DCU_TI]
U7  SN74LVC1G14DBVR  [U_5_DBV]
U1000  SPC02SYAN
sheet P06-IT6535 Input Output Ports
C8  18pF  [0402]
C9  18pF  [0402]
C10  1000pF  [0402]
C11  0.1uF  [0402]
C12  0.1uF  [0402]
C13  0.1uF  [0402]
C14  0.1uF  [0402]
J4  TSM-102-01-T-SV  [CONN2-SMT-TSM-102-SV_SAMTEC]
R14  1M  [0402]
R15  0  [0402]
R16  0  [0402]
R17  10k  [0402]
R18  1.5k  [0603]
R19  DNI  [0402]
R20  4.7k  [0402]
R21  10k  [0402]
R22  500  [0603]
R23  3k  [0402]
R24  4.7k  [0402]
R25  22  [0402]
R26  22  [0402]
R27  22  [0402]
R28  1k  [0402]
R29  10k  [0402]
R30  10k  [0402]
R31  100k  [0603]
R32  0  [0402]
R33  22  [0402]
R34  22  [0402]
RP1  22  [RNET8-EXB-28V]
RP2  22  [RNET8-EXB-28V]
RP3  22  [RNET8-EXB-28V]
RP4  22  [RNET8-EXB-28V]
RP5  22  [RNET8-EXB-28V]
RP6  22  [RNET8-EXB-28V]
RP7  22  [RNET8-EXB-28V]
RP8  22  [RNET8-EXB-28V]
RP9  22  [RNET8-EXB-28V]
RP10  22  [RNET8-EXB-28V]
RP11  22  [RNET8-EXB-28V]
RP12  22  [RNET8-EXB-28V]
RP13  22  [RNET8-EXB-28V]
RP14  22  [RNET8-EXB-28V]
RP15  22  [RNET8-EXB-28V]
TP2  Testpoint  [TP-25RD12]
TP3  Testpoint  [TP-25RD12]
TP4  Testpoint  [TP-25RD12]
TP5  Testpoint  [TP-25RD12]
TP6  Testpoint  [TP-25RD12]
TP7  Testpoint  [TP-25RD12]
TP8  Testpoint  [TP-25RD12]
TP9  Testpoint  [TP-25RD12]
TP10  Testpoint  [TP-25RD12]
U9  M24C02-WMN  [SOIC8]
U10  SN74CB3Q3306  [SOIC8-PW_TI]
X1  27MHz  [OSC4-403-32X25_CTS]
sheet P07-IT6535 Pwr/Gnd
C15  22uF  [0805]
C16  0.1uF  [0402]
C17  0.1uF  [0402]
C18  0.1uF  [0402]
C19  0.1uF  [0402]
C20  0.1uF  [0402]
C21  10uF  [0603]
C22  0.1uF  [0402]
C23  0.1uF  [0402]
C24  0.1uF  [0402]
C25  10uF  [0603]
C26  0.1uF  [0402]
C27  0.1uF  [0402]
C28  0.1uF  [0402]
C29  0.1uF  [0402]
C30  22uF  [0805]
C31  0.1uF  [0402]
C32  0.1uF  [0402]
C33  0.1uF  [0402]
C34  0.1uF  [0402]
C35  0.1uF  [0402]
C36  0.1uF  [0402]
C37  10uF  [0603]
C38  0.1uF  [0402]
C39  0.1uF  [0402]
C40  0.1uF  [0402]
C41  0.1uF  [0402]
C42  10uF  [0603]
C43  0.1uF  [0402]
C44  0.1uF  [0402]
C45  0.1uF  [0402]
C46  10uF  [0603]
C47  0.1uF  [0402]
C48  0.1uF  [0402]
C49  10uF  [0603]
C50  0.1uF  [0402]
C51  0.1uF  [0402]
C52  0.1uF  [0402]
C53  10uF  [0603]
C54  0.1uF  [0402]
C55  0.1uF  [0402]
C56  0.1uF  [0402]
C57  10uF  [0603]
C58  0.1uF  [0402]
C59  0.1uF  [0402]
C60  1.0uF  [0402]
C61  0.1uF  [0402]
C62  1.0uF  [0402]
C63  0.1uF  [0402]
FB2  BKP1005EM221-T  [0402]
FB3  BKP1005EM221-T  [0402]
FB4  BKP1005EM221-T  [0402]
FB5  BKP1005EM221-T  [0402]
FB6  BKP1005EM221-T  [0402]
FB7  BKP1005EM221-T  [0402]
FB8  BKP1005EM221-T  [0402]
FB9  BKP1005EM221-T  [0402]
FB10  BKP1005EM221-T  [0402]
U8  IT6535  [TQFP-176]  (sections A,B,C)
sheet P08-Controller Vid DMD DAD io
C64  15pF  [0402]
C65  15pF  [0402]
C66  15pF  [0402]
C67  15pF  [0402]
C68  15pF  [0402]
C69  15pF  [0402]
C70  15pF  [0402]
C71  15pF  [0402]
C72  15pF  [0402]
C73  15pF  [0402]
C74  15pF  [0402]
R35  4.7k  [0402]
R36  10  [0402]
R37  10  [0402]
R38  10  [0402]
R39  10  [0402]
R40  10  [0402]
R41  10  [0402]
R42  10  [0402]
R43  10  [0402]
R44  10  [0402]
R45  10  [0402]
R46  10  [0402]
TP11  Testpoint  [TP-25RD12]
TP12  Testpoint  [TP-25RD12]
TP13  Testpoint  [TP-25RD12]
TP14  Testpoint  [TP-25RD12]
sheet P09-Controller USB Osc Rst SSP
C75  33pF  [0402]
C76  33pF  [0402]
C77  0.1uF  [0402]
J5  TSM-102-01-T-SV  [CONN2-SMT-TSM-102-SV_SAMTEC]
J6  TMMH-103-01-L-DV  [HDR2X3-TMMH-103-01-L-DV_SAM]
J7  USB Type B Rcpt  [CONN4-USB-897-30-004-90]
R47  1M  [0402]
R48  100  [0603]
R49  33  [0402]
R50  10k  [0402]
R51  10k  [0402]
R52  4.7k  [0402]
R53  4.7k  [0402]
R54  33  [0402]
R55  4.7k  [0402]
R56  1k  [0402]
R57  33  [0402]
R58  33  [0402]
R59  33  [0402]
R60  10k  [0603]
R61  4.7k  [0402]
R62  1.5k  [0603]
R63  22  [2010]
R64  22  [2010]
TP15  Testpoint  [TP-25RD12]
TP16  Testpoint  [TP-25RD12]
U12  SN74AHC1G125DBVR  [SOIC5-DBV_TI]
U13  SN65220DBVT  [SOIC6-DBV_TI]
X2  445I23D20M00000  [CRY2-445-32X5_CTS]
sheet P10-Controller Ext Flash Intf
U11  DLPC900  [BGA516-DDP_TI]  (sections A,B,C,D,E,F,G,H,I,J)
sheet P13-Controller Pwr/Gnd
C88  100uF  [1206]
C89  10uF  [0603]
C90  0.1uF  [0402]
C91  0.1uF  [0402]
C92  0.1uF  [0402]
C93  0.1uF  [0402]
C94  0.1uF  [0402]
C95  0.1uF  [0402]
C96  0.1uF  [0402]
C97  0.1uF  [0402]
C98  0.1uF  [0402]
C99  0.1uF  [0402]
C100  0.1uF  [0402]
C101  0.1uF  [0402]
C102  0.1uF  [0402]
C103  10uF  [0603]
C104  0.1uF  [0402]
C105  0.1uF  [0402]
C106  0.1uF  [0402]
C107  0.1uF  [0402]
C108  0.1uF  [0402]
C109  0.1uF  [0402]
C110  0.1uF  [0402]
C111  0.1uF  [0402]
C112  0.1uF  [0402]
C113  0.1uF  [0402]
C114  0.1uF  [0402]
C115  0.1uF  [0402]
C116  0.1uF  [0402]
C117  100uF  [1206]
C118  0.1uF  [0402]
C119  0.1uF  [0402]
C120  10uF  [0603]
C121  0.1uF  [0402]
C122  0.1uF  [0402]
C123  0.1uF  [0402]
C124  0.1uF  [0402]
C125  0.1uF  [0402]
C126  0.1uF  [0402]
C127  0.1uF  [0402]
C128  0.1uF  [0402]
C129  0.1uF  [0402]
C130  0.1uF  [0402]
C131  100uF  [1206]
C132  0.1uF  [0402]
C133  0.1uF  [0402]
C134  100uF  [1206]
C135  0.1uF  [0402]
C136  10uF  [0603]
C137  0.1uF  [0402]
C138  0.1uF  [0402]
C139  0.1uF  [0402]
C140  0.1uF  [0402]
C141  0.1uF  [0402]
C142  0.1uF  [0402]
C143  0.1uF  [0402]
C144  0.1uF  [0402]
C145  0.1uF  [0402]
C146  0.1uF  [0402]
C147  2.2uF  [0603]
C148  2.2uF  [0603]
C149  0.1uF  [0402]
C150  0.1uF  [0402]
C151  0.1uF  [0402]
C152  0.1uF  [0402]
C153  0.1uF  [0402]
C154  0.1uF  [0402]
C155  0.1uF  [0402]
C156  0.1uF  [0402]
C157  0.1uF  [0402]
C158  0.1uF  [0402]
C159  0.1uF  [0402]
FB11  BK1005HS431-T  [0402]
FB12  BK1005HS431-T  [0402]
FB13  BK1005HS431-T  [0402]
FB14  BK1005HS431-T  [0402]
FB15  BK1005HS431-T  [0402]
FB16  BK1005HS431-T  [0402]
FB17  BK1005HS431-T  [0402]
R109  0.36  [0402]
R110  1.0  [0402]

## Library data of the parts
C1-C5 C7 C11 C14 = CER_0.1UF_25V_10%_X5R_0402: ALT_SYMBOLS: 0402-1MM
C6 C60 C62 = CER_1.0UF_16V_10%_X5R_0402: ALT_SYMBOLS: 0402-1MM
D1-D4 = TVS_ZENER_DUAL_SOT323
F1 = Fuse_Polyswitch.75A
FB1 = FERRITE_BEAD_220_OHM_800mA_0402: ALT_SYMBOLS: 0402-1MM
J1 = HDMI_Connector_0
J2 = DP_CONN_RCPT_R_A_W_O_FLANGE: Digikey Part Number: WM19271TR-ND; MFG: Molex; MFG Part Number: 0472720001
J3-J5 = TSM-102-01-T-SV_2POS_.1_SMD
R1 R5 R6 R28 R56 = 1.0K_OHM_1_16W_5%_0402: ALT_SYMBOLS: 0402-1MM
R2 R3 R10 R13 R14 R47 = 1M_OHM_1_10W_5%_0402: ALT_SYMBOLS: 0402-1MM
R4 = 200K_OHM_1_16W_5%_0402: ALT_SYMBOLS: 0402-1MM
R7 R8 R12 R17 R21 R29 R30 R50 R51 = 10K_OHM_1_10W_5%_0402: ALT_SYMBOLS: 0402-1MM
R9 = 0.0_OHM_1_10W_0603
R11 R15 R16 R32 = 0.0_OHM_1_10W_0402: ALT_SYMBOLS: 0402-1MM
TP1-TP16 = Testpoint
U1-U4 = TPD4S010DQA
U5 U9 = M24C08L_dsize
U6 = PCA9306DCUR
U7 = IC_SGL_SHMT-TRG_INV_SOT23-5
U1000 = DLP026_0: MFG: TI
C8 C9 = CER_18PF_50V_5%_NP0_0402: ALT_SYMBOLS: 0402-1MM
C10 = CER_1000PF_25V_10%_X7R_0402: ALT_SYMBOLS: 0402-1MM
C12 C13 C16-C20 C22-C24 C26-C29 C31-C36 C38-C41 C43-C45 C47 C48 C50-C52 C54-C56 C58 C59 C61 C63 C77 C90-C102 C104-C116 C118 C119 C121-C130 C132 C133 C135 C137-C146 C149-C159 = CER_0.1UF_16V_10%_X5R_0402: ALT_SYMBOLS: 0402-1MM
R18 R62 = 1.5K_OHM_1_10W_5%_0603
R19 R20 R24 R35 R52 R53 R55 R61 = 4.7K_OHM_1_10W_5%_0402: ALT_SYMBOLS: 0402-1MM
R22 = 500_OHM_0.15W_0.05%_0603
R23 = 3K_OHM_1_16W_5%_0402: ALT_SYMBOLS: 0402-1MM
R25-R27 R33 R34 = 22_OHM_1_10W_1%_0402: ALT_SYMBOLS: 0402-1MM
R31 = 100K_OHM_1_10W_1%_0603
RP1-RP15 = 22_OHM_ARR_1_32W_5%_0804
U10 = IC_DUAL_FET_BUS_SWITCH_8-TSSOP
X1 = CRYSTAL_27MHZ_18PF_SMD
C15 C30 = CER_22UF_16V_10%_X5R_0805
C21 C25 C37 C49 = CER_10UF_16V_20%_X5R_0603
C42 C46 C53 C57 C89 C103 C120 C136 = CER_10UF_10V_20%_X5R_0603
FB2-FB10 = FERRITE_BEAD_220_OHM_1A_0402: ALT_SYMBOLS: 0402-1MM
U8 = IT6535: Color: Default; Location X-Coordinate: 0; Location Y-Coordinate: 0; Power Pins Visible: False; Primitive: DEFAULT
C64-C74 = CER_15PF_16V_5%_NP0_0402: ALT_SYMBOLS: 0402-1MM
R36-R46 = 10.0_OHM_1_16W_1%_0402: ALT_SYMBOLS: 0402-1MM
C75 C76 = CER_33PF_50V_1%_NP0_0402: ALT_SYMBOLS: 0402-1MM
J6 = TMMH-103-01-L-DV_6POS_2ROWS_2MM
J7 = USB_RCPT_B-TYPE_R_A
R48 = 100_OHM_1_10W_5%_0603
R49 R54 R57-R59 = 33_OHM_1_16W_5%_0402: ALT_SYMBOLS: 0402-1MM
R60 = 10K_OHM_1_10W_5%_0603
R63 R64 = 22.0_OHM_3_4W_1%_2010
U12 = 74AHC1G125
U13 = SN65220_USB_PORT_TVS
X2 = CTS_CRYSTAL_20MHZ_18PF_SMD
U11 = DLPC900_910_datasheet
C88 C117 C131 C134 = CER_100UF_6.3V_20%_X5R_1206
C147 C148 = CER_2.2UF_25V_10%_X5R_0603
FB11-FB17 = FERRITE_BEAD_430OHM_0402: ALT_SYMBOLS: 0402-1MM
R109 = 0.36_OHM_1_8W_1%_0402: ALT_SYMBOLS: 0402-1MM
R110 = 1.00_OHM_1_16W_1%_0402: ALT_SYMBOLS: 0402-1MM

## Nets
GND: C1.2 C2.2 C3.2 C4.2 C5.2 C6.2 C7.2 C8.1 C9.1 C10.2 C11.2 C14.2 C15.2 C16.2 C17.2 C18.2 C19.2 C20.2 C21.2 C22.2 C23.2 C24.2 C25.2 C26.2 C27.2 C28.2 C29.2 C30.2 C31.2 C32.2 C33.2 C34.2 C35.2 C36.2 C37.2 C38.2 C39.2 C40.2 C41.2 C42.2 C43.2 C44.2 C45.2 C46.2 C47.2 C48.2 C49.2 C50.2 C51.2 C52.2 C53.2 C54.2 C55.2 C56.2 C57.2 C58.2 C59.2 C60.2 C61.2 C62.2 C63.2 C64.2 C65.2 C66.2 C67.2 C68.2 C69.2 C70.2 C71.2 C72.2 C73.2 C74.2 C75.2 C76.2 C77.2 C88.2 C89.2 C90.2 C91.2 C92.2 C93.2 C94.2 C95.2 C96.2 C97.2 C98.2 C99.2 C100.2 C101.2 C102.2 C103.2 C104.2 C105.2 C106.2 C107.2 C108.2 C109.2 C110.2 C111.2 C112.2 C113.2 C114.2 C115.2 C116.2 C117.2 C118.2 C119.2 C120.2 C121.2 C122.2 C123.2 C124.2 C125.2 C126.2 C127.2 C128.2 C129.2 C130.2 C131.2 C132.2 C133.2 C134.2 C135.2 C136.2 C137.2 C138.2 C139.2 C140.2 C141.2 C142.2 C143.2 C144.2 C145.2 C146.2 C147.2 C148.2 C149.2 C150.2 C151.2 C152.2 C153.2 C154.2 C155.2 C156.2 C157.2 C158.2 C159.2 D1.3 D2.3 D3.3 D4.3 J1.2(D2_Shield) J1.5(D1_Shield) J1.8(D0_Shield) J1.11(CK_Shield) J1.17(GND) J1.20(MTG1) J1.21(MTG2) J1.22(MTG3) J1.23(MTG4) J2.2(GND2) J2.5(GND5) J2.8(GND8) J2.11(GND11) J2.16(GND16) J2.19(RETURN) J2.21(MTG1) J2.22(MTG2) J2.23(MTG3) J2.24(MTG4) J3.2 J4.2 J5.2 J6.6 J7.4 R2.2 R3.2 R9.2 R12.2 R13.2 R20.2 R21.2 R22.2 R23.2 R24.2 R31.2 R51.2 R60.2 U1.3(GND) U1.8(GND) U2.3(GND) U2.8(GND) U3.3(GND) U3.8(GND) U4.3(GND) U4.8(GND) U5.2(E1) U5.3(E2) U5.4(VSS) U6.1(GND) U7.3(GND) U8.2(OVSS) U8.12(IVSS) U8.21(OVSS) U8.37(IVSS) U8.39(OVSS) U8.68(OVSS) U8.71(IVSS) U8.72(IVSS) U8.87(AVSS) U8.92(AVSS) U8.95(AVSS) U8.99(AVSS) U8.105(PVSS) U8.107(IVSS) U8.110(PGND) U8.113(DVSS18) U8.117(AGND) U8.123(AGND) U8.127(DVSS18) U8.130(PGND) U8.148(OVSS) U8.150(IVSS) U8.163(OVSS) U9.1(E0) U9.2(E1) U9.3(E2) U9.4(VSS) U10.4(GND) U11.A1(GND) U11.A2(GND) U11.A3(GND) U11.A17(L_VDQPAD_1) U11.A18(L_VDQPAD_3) U11.A24(GND) U11.A25(GND) U11.A26(GND) U11.AA6(GND) U11.AA9(GND) U11.AA12(GND) U11.AA15(GND) U11.AA18(GND) U11.AA21(GND) U11.AB5(GND) U11.AB14(VTEST1) U11.AB15(VTEST2) U11.AB16(R_VDQPAD_3) U11.AB17(R_VDQPAD_1) U11.AB22(GND) U11.AC4(GND) U11.AC17(R_VDQPAD_6) U11.AC18(R_VDQPAD_4) U11.AC23(GND) U11.AD3(GND) U11.AD17(R_VDQPAD_2) U11.AD18(R_VDQPAD_0) U11.AD24(GND) U11.AE3(GND) U11.AE17(R_VDQPAD_7) U11.AE24(GND) U11.AE25(GND) U11.AF1(GND) U11.AF2(GND) U11.AF3(GND) U11.AF17(R_VDQPAD_5) U11.AF24(GND) U11.AF25(GND) U11.AF26(GND) U11.B1(GND) U11.B2(GND) U11.B3(GND) U11.B17(L_VDQPAD_5) U11.B18(L_VDQPAD_7) U11.B25(GND) U11.C3(GND) U11.C18(L_VDQPAD_2) U11.C24(GND) U11.D4(GND) U11.D17(L_VDQPAD_0) U11.D18(L_VDQPAD_6) U11.D23(GND) U11.E5(GND) U11.E15(VTEST3) U11.E16(VTEST4) U11.E17(L_VDQPAD_4) U11.E22(GND) U11.F6(GND) U11.F9(GND) U11.F12(GND) U11.F15(GND) U11.F18(GND) U11.F21(GND) U11.G5(GND) U11.J5(GND) U11.J6(GND) U11.J21(GND) U11.K5(LVDS_AVS1) U11.K26(PLLD_VAS) U11.L5(GND) U11.L12(GND) U11.L13(GND) U11.L14(GND) U11.L15(GND) U11.L23(PLLD_VSS) U11.L25(PLLM1_VAS) U11.M6(GND) U11.M11(GND) U11.M12(GND) U11.M13(GND) U11.M14(GND) U11.M15(GND) U11.M16(GND) U11.M21(GND) U11.M22(PLLM1_VSS) U11.N5(GND) U11.N11(GND) U11.N12(GND) U11.N13(GND) U11.N14(GND) U11.N15(GND) U11.N16(GND) U11.P11(GND) U11.P12(GND) U11.P13(GND) U11.P14(GND) U11.P15(GND) U11.P16(GND) U11.P24(PLLM2_VSS) U11.R5(GND) U11.R6(GND) U11.R11(GND) U11.R12(GND) U11.R13(GND) U11.R14(GND) U11.R15(GND) U11.R16(GND) U11.R24(PLLS_VAS) U11.R26(PLLM2_VAS) U11.T12(GND) U11.T13(GND) U11.T14(GND) U11.T15(GND) U11.U5(GND) U11.V5(LVDS_AVS2) U11.V6(GND) U11.V21(GND) U11.W5(GND) U11.Y5(GND) U12.3(GND) U13.2(GND2) U13.5(GND5) ; also on sheet 2 4 5 6 7 8 9 10 11
AFE_ARSTZ: R35.2 U8.74(SYSRSTN) U11.AC12(AFE_ARSTZ) ; also on sheet 2
DADADDR0: R36.2 ; also on sheet 6
DADADDR1: R37.2 ; also on sheet 6
DADADDR2: R38.2 ; also on sheet 6
DADADDR3: R39.2 ; also on sheet 6
DADINTZ: R46.2 ; also on sheet 6
DADMODE0: R40.2 ; also on sheet 6
DADMODE1: R41.2 ; also on sheet 6
DADOEZ: R45.2 ; also on sheet 6
DADSEL0: R42.2 ; also on sheet 6
DADSEL1: R43.2 ; also on sheet 6
DADSTRB: R44.2 TP14.1 ; also on sheet 6
DP_DDCSCL: R29.2 U8.79(DDCSCL) U9.6(SCL) U10.2(1A)
DP_DDCSDA: R30.2 U8.80(DDCSDA) U9.5(SDA) U10.5(2A)
DP_EDID_WE: J4.1 R28.2 R32.1 U9.7(WC/)
DP_RXAUXN: C13.1 U8.108(RXAUXN)
DP_RXAUXP: C12.1 U8.109(RXAUXP)
DPCON_CONFIG1: J2.13(CONFIG1) R2.1
DPCON_CONFIG2: J2.14(CONFIG2) R3.1
DPIICWR_OEZ: R32.2 U10.1(1~{OE}) U10.7(2~{OE})
DRX_AUXN: C13.2 D4.2 J2.17(AUX-) R13.1 U8.82(DCAUXN)
DRX_AUXP: C12.2 D4.1 J2.15(AUX+) R10.2 U8.83(DCAUXP)
DRX_HPD: D2.1 J2.18(HPD) R31.1 TP10.1 U8.81(HPD)
DRX_LN0N: J2.10(LANE0-) U4.2(D1-) U4.9(NC) U8.116(DRX0N)
DRX_LN0P: J2.12(LANE0+) U4.1(D1+) U4.10(NC) U8.115(DRX0P)
DRX_LN1N: J2.7(LANE1-) U4.5(D2-) U4.6(NC) U8.119(DRX1N)
DRX_LN1P: J2.9(LANE1+) U4.4(D2+) U4.7(NC) U8.118(DRX1P)
DRX_LN2N: J2.4(LANE2-) U3.2(D1-) U3.9(NC) U8.122(DRX2N)
DRX_LN2P: J2.6(LANE2+) U3.1(D1+) U3.10(NC) U8.121(DRX2P)
DRX_LN3N: J2.1(LANE3-) U3.5(D2-) U3.6(NC) U8.125(DRX3N)
DRX_LN3P: J2.3(LANE3+) U3.4(D2+) U3.7(NC) U8.124(DRX3P)
DRX_PWR: D2.2 F1.2 J2.20(DP_PWR)
HDMI_5V: C2.1 C5.1 C6.1 FB1.2 R5.1 R6.1 R7.1 R8.1 R18.1 TP1.1 U5.8(VCC) U7.5(VCC)
HDMI_CEC: U11.G23(RESERVED) ; also on sheet 2
HDMI_INTZ: R17.1 TP9.1 U8.75(INT#) U11.AB13(AFE_IRQ) ; also on sheet 2
HEDID_I2C_EN: C3.1 R4.2 U6.7(VREF2) U6.8(EN)
HEDID_VREF2: C7.1 R4.1 R12.1 U7.4
HEDID_WE: J3.1 R6.2 R11.1 U5.7(WC/) U7.2
HRX_5V: C1.1 D1.1 FB1.1 J1.18(+5V) R1.2
HRX_CKN: J1.12(CK-) U1.5(D2-) U1.6(NC) U8.90(HRXCM)
HRX_CKP: J1.10(CK+) U1.4(D2+) U1.7(NC) U8.91(HRXCP)
HRX_D0N: J1.9(D0-) U1.2(D1-) U1.9(NC) U8.93(HRX0M)
HRX_D0P: J1.7(D0+) U1.1(D1+) U1.10(NC) U8.94(HRX0P)
HRX_D1N: J1.6(D1-) U2.5(D2-) U2.6(NC) U8.97(HRX1M)
HRX_D1P: J1.4(D1+) U2.4(D2+) U2.7(NC) U8.98(HRX1P)
HRX_D2N: J1.3(D2-) U2.2(D1-) U2.9(NC) U8.101(HRX2M)
HRX_D2P: J1.1(D2+) U2.1(D1+) U2.10(NC) U8.102(HRX2P)
HRX_DDCCLK: D3.2 J1.15(DDC_CLK) R7.2 R15.1 U5.6(SCL) U6.6(SCL2)
HRX_DDCDAT: D3.1 J1.16(DDC_DATA) R8.2 R16.1 U5.5(SDA) U6.5(SDA2)
HRX_HPD: D1.2 J1.19(HP_DET) R1.1 R11.2 ; also on sheet 2
HRXDDCSCL: R15.2 U8.85(RXDDCSCL)
HRXDDCSDA: R16.2 U8.84(RXDDCSDA)
IT_DE_PIN: R26.1 U8.5(DE)
IT_EMEMVPP: R21.1 U8.49(EMEM_VPP)
IT_ENTEST: R20.1 U8.73(ENTEST)
IT_FIELD_PIN: R25.1 U8.3(FIELD)
IT_HS_PIN: RP8.3 U8.7(HSYNC)
IT_PCADR: R19.2 R24.1 U8.76(PCADR)
IT_PCLK: R27.1 U8.4(PCLK)
IT_PWR5V: C10.1 R18.2 R23.1 U8.86(PWR5V)
IT_REXT: R22.1 U8.103(REXT)
IT_VS_PIN: RP8.4 U8.6(VSYNC)
IT_XTALIN: C8.2 R14.1 U8.132(XTALIN) X1.3
IT_XTALOUT: C9.2 R14.2 U8.131(XTALOUT) X1.1
ITE_ASPVCC: C60.1 C61.1 FB9.2 U8.133(ASPVCC)
ITE_AVCC: C42.1 C43.1 C44.1 C45.1 FB4.2 U8.114(AVCC_1P8) U8.120(AVCC_1P8) U8.126(AVCC_1P8)
ITE_AVCC18: C53.1 C54.1 C55.1 C56.1 FB7.2 U8.88(AVCC18)
ITE_AVCC33: C49.1 C50.1 C51.1 C52.1 FB6.2 U8.89(AVCC33) U8.96(AVCC33) U8.100(AVCC33)
ITE_DVDD1P8: C46.1 C47.1 C48.1 FB5.2 U8.112(DVDD18) U8.128(DVDD18)
ITE_IVDD1P8: C30.1 C31.1 C32.1 C33.1 C34.1 C35.1 C36.1 FB3.2 U8.11(IVDD_1P8) U8.36(IVDD_1P8) U8.69(IVDD_1P8) U8.70(IVDD_1P8) U8.106(IVDD_1P8) U8.149(IVDD_1P8)
ITE_OVDD3P3: C15.1 C16.1 C17.1 C18.1 C19.1 C20.1 C23.1 FB2.2 U8.1(OVDD_3P3) U8.20(OVDD_3P3) U8.38(OVDD_3P3) U8.67(OVDD_3P3) U8.147(OVDD_3P3) U8.162(OVDD_3P3)
ITE_PVCC: C57.1 C58.1 C59.1 FB8.2 U8.111(PVCC) U8.129(PVCC)
ITE_PVCC18: C62.1 C63.1 FB10.2 U8.104(PVCC18)
M_1P1V_FILTER: C117.1 C118.1 FB11.1 FB13.1 FB15.1 FB17.1 R109.2
M_1P8V_A_FILTER: C131.1 C132.1 FB12.1 FB14.1 FB16.1 R110.2
M_CW_PWM: TP15.1 U11.AD8(RESERVED)
M_DADA0: C67.1 R36.1 U11.AB8(DADADDR_0)
M_DADA1: C66.1 R37.1 U11.AF4(DADADDR_1)
M_DADA2: C65.1 R38.1 U11.AE5(DADADDR_2)
M_DADA3: C64.1 R39.1 U11.AD6(DADADDR_3)
M_DADINTZ: C68.1 R46.1 U11.AC8(DAD_INTZ)
M_DADM0: C74.1 R40.1 U11.AE6(DADMODE_0)
M_DADM1: C73.1 R41.1 U11.AD7(DADMODE_1)
M_DADOEZ: C69.1 R45.1 U11.AE7(DADOEZ)
M_DADSEL0: C72.1 R42.1 U11.AC7(DADSEL_0)
M_DADSEL1: C71.1 R43.1 U11.AE4(DADSEL_1)
M_DADSTB: C70.1 R44.1 U11.AF5(DADSTRB)
M_DCLKA_N: U11.J4(DCKB_N) ; also on sheet 6
M_DCLKA_P: U11.J3(DCKB_P) ; also on sheet 6
M_DCLKB_N: U11.V3(DCKA_N) ; also on sheet 6
M_DCLKB_P: U11.V4(DCKA_P) ; also on sheet 6
M_DDA00_N: U11.N2(DDB_N_15) ; also on sheet 6
M_DDA00_P: U11.N1(DDB_P_15) ; also on sheet 6
M_DDA01_N: U11.N4(DDB_N_14) ; also on sheet 6
M_DDA01_P: U11.N3(DDB_P_14) ; also on sheet 6
M_DDA02_N: U11.M1(DDB_N_13) ; also on sheet 6
M_DDA02_P: U11.M2(DDB_P_13) ; also on sheet 6
M_DDA03_N: U11.M4(DDB_N_12) ; also on sheet 6
M_DDA03_P: U11.M3(DDB_P_12) ; also on sheet 6
M_DDA04_N: U11.L2(DDB_N_11) ; also on sheet 6
M_DDA04_P: U11.L1(DDB_P_11) ; also on sheet 6
M_DDA05_N: U11.L4(DDB_N_10) ; also on sheet 6
M_DDA05_P: U11.L3(DDB_P_10) ; also on sheet 6
M_DDA06_N: U11.K2(DDB_N_9) ; also on sheet 6
M_DDA06_P: U11.K1(DDB_P_9) ; also on sheet 6
M_DDA07_N: U11.K4(DDB_N_8) ; also on sheet 6
M_DDA07_P: U11.K3(DDB_P_8) ; also on sheet 6
M_DDA08_N: U11.H2(DDB_N_7) ; also on sheet 6
M_DDA08_P: U11.H1(DDB_P_7) ; also on sheet 6
M_DDA09_N: U11.H4(DDB_N_6) ; also on sheet 6
M_DDA09_P: U11.H3(DDB_P_6) ; also on sheet 6
M_DDA10_N: U11.G2(DDB_N_5) ; also on sheet 6
M_DDA10_P: U11.G1(DDB_P_5) ; also on sheet 6
M_DDA11_N: U11.G4(DDB_N_4) ; also on sheet 6
M_DDA11_P: U11.G3(DDB_P_4) ; also on sheet 6
M_DDA12_N: U11.F2(DDB_N_3) ; also on sheet 6
M_DDA12_P: U11.F1(DDB_P_3) ; also on sheet 6
M_DDA13_N: U11.F4(DDB_N_2) ; also on sheet 6
M_DDA13_P: U11.F3(DDB_P_2) ; also on sheet 6
M_DDA14_N: U11.E2(DDB_N_1) ; also on sheet 6
M_DDA14_P: U11.E1(DDB_P_1) ; also on sheet 6
M_DDA15_N: U11.D2(DDB_N_0) ; also on sheet 6
M_DDA15_P: U11.D1(DDB_P_0) ; also on sheet 6
M_DDB00_N: U11.P3(DDA_N_15) ; also on sheet 6
M_DDB00_P: U11.P4(DDA_P_15) ; also on sheet 6
M_DDB01_N: U11.P1(DDA_N_14) ; also on sheet 6
M_DDB01_P: U11.P2(DDA_P_14) ; also on sheet 6
M_DDB02_N: U11.R3(DDA_N_13) ; also on sheet 6
M_DDB02_P: U11.R4(DDA_P_13) ; also on sheet 6
M_DDB03_N: U11.R1(DDA_N_12) ; also on sheet 6
M_DDB03_P: U11.R2(DDA_P_12) ; also on sheet 6
M_DDB04_N: U11.T3(DDA_N_11) ; also on sheet 6
M_DDB04_P: U11.T4(DDA_P_11) ; also on sheet 6
M_DDB05_N: U11.T1(DDA_N_10) ; also on sheet 6
M_DDB05_P: U11.T2(DDA_P_10) ; also on sheet 6
M_DDB06_N: U11.U3(DDA_N_9) ; also on sheet 6
M_DDB06_P: U11.U4(DDA_P_9) ; also on sheet 6
M_DDB07_N: U11.U1(DDA_N_8) ; also on sheet 6
M_DDB07_P: U11.U2(DDA_P_8) ; also on sheet 6
M_DDB08_N: U11.W3(DDA_N_7) ; also on sheet 6
M_DDB08_P: U11.W4(DDA_P_7) ; also on sheet 6
M_DDB09_N: U11.W1(DDA_N_6) ; also on sheet 6
M_DDB09_P: U11.W2(DDA_P_6) ; also on sheet 6
M_DDB10_N: U11.Y1(DDA_N_5) ; also on sheet 6
M_DDB10_P: U11.Y2(DDA_P_5) ; also on sheet 6
M_DDB11_N: U11.Y3(DDA_N_4) ; also on sheet 6
M_DDB11_P: U11.Y4(DDA_P_4) ; also on sheet 6
M_DDB12_N: U11.AA1(DDA_N_3) ; also on sheet 6
M_DDB12_P: U11.AA2(DDA_P_3) ; also on sheet 6
M_DDB13_N: U11.AA3(DDA_N_2) ; also on sheet 6
M_DDB13_P: U11.AA4(DDA_P_2) ; also on sheet 6
M_DDB14_N: U11.AB1(DDA_N_1) ; also on sheet 6
M_DDB14_P: U11.AB2(DDA_P_1) ; also on sheet 6
M_DDB15_N: U11.AC1(DDA_N_0) ; also on sheet 6
M_DDB15_P: U11.AC2(DDA_P_0) ; also on sheet 6
M_EXT_RSTZ: R52.1 U11.T24(EXT_RSTZ) ; also on sheet 6
M_FIELD_GPIO78: R25.2 U11.AF9(RESERVED) ; also on sheet 2
M_OCLKA_PIN: R49.1 U11.AF6(OCLKA)
M_P1A0: RP3.7 U11.AE12(P1_A0) ; also on sheet 2
M_P1A1: RP3.8 U11.AF12(P1_A1) ; also on sheet 2
M_P1A2: RP2.5 U11.AF13(P1_A2) ; also on sheet 2
M_P1A3: RP2.6 U11.AF14(P1_A3) ; also on sheet 2
M_P1A4: RP2.7 U11.AC13(P1_A4) ; also on sheet 2
M_P1A5: RP2.8 U11.AD13(P1_A5) ; also on sheet 2
M_P1A6: RP1.5 U11.AE13(P1_A6) ; also on sheet 2
M_P1A7: RP1.6 U11.AE14(P1_A7) ; also on sheet 2
M_P1A8: RP1.7 U11.AE15(P1_A8) ; also on sheet 2
M_P1A9: RP1.8 U11.AD15(P1_A9) ; also on sheet 2
M_P1B0: RP5.5 U11.AD14(P1_B0) ; also on sheet 2
M_P1B1: RP5.6 U11.AC14(P1_B1) ; also on sheet 2
M_P1B2: RP5.7 U11.AF15(P1_B2) ; also on sheet 2
M_P1B3: RP5.8 U11.AF16(P1_B3) ; also on sheet 2
M_P1B4: RP4.5 U11.AE16(P1_B4) ; also on sheet 2
M_P1B5: RP4.6 U11.AD16(P1_B5) ; also on sheet 2
M_P1B6: RP4.7 U11.AC16(P1_B6) ; also on sheet 2
M_P1B7: RP4.8 U11.AC15(P1_B7) ; also on sheet 2
M_P1B8: RP3.5 U11.AB18(P1_B8) ; also on sheet 2
M_P1B9: RP3.6 U11.AF18(P1_B9) ; also on sheet 2
M_P1C0: RP8.7 U11.AE18(P1_C0) ; also on sheet 2
M_P1C1: RP8.8 U11.AC19(P1_C1) ; also on sheet 2
M_P1C2: RP7.5 U11.AF20(P1_C2) ; also on sheet 2
M_P1C3: RP7.6 U11.AF19(P1_C3) ; also on sheet 2
M_P1C4: RP7.7 U11.AE19(P1_C4) ; also on sheet 2
M_P1C5: RP7.8 U11.AD19(P1_C5) ; also on sheet 2
M_P1C6: RP6.5 U11.AF21(P1_C6) ; also on sheet 2
M_P1C7: RP6.6 U11.AE21(P1_C7) ; also on sheet 2
M_P1C8: RP6.7 U11.AE20(P1_C8) ; also on sheet 2
M_P1C9: RP6.8 U11.AD20(P1_C9) ; also on sheet 2
M_P1DATEN: R26.2 TP12.1 U11.AF22(P_DATAEN1) ; also on sheet 2
M_P1HS: RP8.6 U11.AD21(P1_HSYNC) ; also on sheet 2
M_P1VS: RP8.5 TP13.1 U11.AC20(P1_VSYNC) ; also on sheet 2
M_P2A0: RP11.7 U11.AB19(P2_A0) ; also on sheet 2
M_P2A1: RP11.8 U11.AE23(P2_A1) ; also on sheet 2
M_P2A2: RP10.5 U11.AD22(P2_A2) ; also on sheet 2
M_P2A3: RP10.6 U11.AC21(P2_A3) ; also on sheet 2
M_P2A4: RP10.7 U11.AB20(P2_A4) ; also on sheet 2
M_P2A5: RP10.8 U11.AD23(P2_A5) ; also on sheet 2
M_P2A6: RP9.5 U11.AC22(P2_A6) ; also on sheet 2
M_P2A7: RP9.6 U11.AB21(P2_A7) ; also on sheet 2
M_P2A8: RP9.7 U11.AD25(P2_A8) ; also on sheet 2
M_P2A9: RP9.8 U11.AD26(P2_A9) ; also on sheet 2
M_P2B0: RP13.5 U11.AC24(P2_B0) ; also on sheet 2
M_P2B1: RP13.6 U11.AC25(P2_B1) ; also on sheet 2
M_P2B2: RP13.7 U11.AB23(P2_B2) ; also on sheet 2
M_P2B3: RP13.8 U11.AC26(P2_B3) ; also on sheet 2
M_P2B4: RP12.5 U11.AB24(P2_B4) ; also on sheet 2
M_P2B5: RP12.6 U11.AA22(P2_B5) ; also on sheet 2
M_P2B6: RP12.7 U11.AB25(P2_B6) ; also on sheet 2
M_P2B7: RP12.8 U11.AA23(P2_B7) ; also on sheet 2
M_P2B8: RP11.5 U11.AB26(P2_B8) ; also on sheet 2
M_P2B9: RP11.6 U11.Y22(P2_B9) ; also on sheet 2
M_P2C0: R34.2 U11.AA24(P2_C0) ; also on sheet 2
M_P2C1: R33.2 U11.AA25(P2_C1) ; also on sheet 2
M_P2C2: RP15.5 U11.AA26(P2_C2) ; also on sheet 2
M_P2C3: RP15.6 U11.W22(P2_C3) ; also on sheet 2
M_P2C4: RP15.7 U11.Y23(P2_C4) ; also on sheet 2
M_P2C5: RP15.8 U11.Y24(P2_C5) ; also on sheet 2
M_P2C6: RP14.5 U11.Y25(P2_C6) ; also on sheet 2
M_P2C7: RP14.6 U11.Y26(P2_C7) ; also on sheet 2
M_P2C8: RP14.7 U11.V22(P2_C8) ; also on sheet 2
M_P2C9: RP14.8 U11.W23(P2_C9) ; also on sheet 2
M_P2DATEN: U11.W24(P_DATAEN2) ; also on sheet 2
M_P2HS: U11.W26(P2_HSYNC) ; also on sheet 2
M_P2VS: U11.U22(P2_VSYNC) ; also on sheet 2
M_PCLK1: R27.2 TP11.1 U11.AE22(P_CLK1) ; also on sheet 2
M_PCLK2: U11.W25(P_CLK2) ; also on sheet 2
M_PMDINTZ: R50.2 U11.AE8(RESERVED)
M_POSENSE: U11.P22(POSENSE) ; also on sheet 8 11
M_SCL1: U6.3(SCL1) U8.77(PCSCL) U10.3(1B) ; also on sheet 2 9
M_SCTLA_N: U11.J2(SCB_N) ; also on sheet 6
M_SCTLA_P: U11.J1(SCB_P) ; also on sheet 6
M_SCTLB_N: U11.V1(SCA_N) ; also on sheet 6
M_SCTLB_P: U11.V2(SCA_P) ; also on sheet 6
M_SDA1: U6.4(SDA1) U8.78(PCSDA) U10.6(2B) ; also on sheet 2 9
M_SSP0_CLK: R57.1 U11.AD4(SSP0_CLK)
M_SSP0_CSZ0: R53.2 R59.1 U11.AC5(SSP0_CSZ_0)
M_SSP0_CSZ1: R55.2 R58.1 U11.AB6(SSP0_CSZ_1)
M_SSP0_TXD: R54.1 U11.AB7(SSP0_TXD)
M_UART0_CTSZ: J6.4 R51.1 U11.AE2(UART0_CTSZ)
M_UART0_RTSZ: J6.5 U11.AD2(UART0_RTSZ)
M_UART0_RXD: J6.3 U11.AD1(UART0_RXD)
M_UART0_TXD: J6.2 U11.AB3(UART0_TXD)
M_USB_ENZ: R61.1 U12.1(~{OE}) ; also on sheet 9
M_USB_N: R63.2 U11.C5(USB_DAT_N)
M_USB_P: R64.2 U11.D6(USB_DAT_P)
MOSCN: R47.2 R48.2 U11.N26(MOSCN)
MOSCP: C75.1 R47.1 U11.M26(MOSCP) X2.2
OCLKA: J5.1 R49.2
P1P8V: C25.1 C26.1 C27.1 C28.1 C29.1 C120.1 C121.1 C122.1 C123.1 C124.1 C125.1 C126.1 C127.1 C128.1 C129.1 C130.1 C134.1 C136.1 C137.1 C138.1 C139.1 C140.1 C141.1 C142.1 C143.1 C144.1 FB3.1 FB5.1 U11.AA5(LVDSAVD) U11.AA13(DRAMVDD) U11.AE1(LVDSAVD) U11.C1(LVDSAVD) U11.F5(LVDSAVD) U11.F14(DRAMVDD) U11.G6(LVDSAVD) U11.H5(DRAMVDD) U11.H21(DRAMVDD) U11.K6(LVDSAVD) U11.M5(LVDSAVD) U11.N6(DRAMVDD) U11.P5(LVDSAVD) U11.P21(DRAMVDD) U11.T5(LVDSAVD) U11.T6(DRAMVDD) U11.U21(DRAMVDD) U11.W6(LVDSAVD) ; also on sheet 5 7
P1P8V_A: R110.1 ; also on sheet 4
P1P8V_ITEA: C37.1 C38.1 C39.1 C40.1 C41.1 FB4.1 FB7.1 FB8.1 FB9.1 FB10.1 ; also on sheet 4
P1P15V: C88.1 C89.1 C90.1 C91.1 C92.1 C93.1 C94.1 C95.1 C96.1 C97.1 C98.1 C99.1 C100.1 C101.1 C103.1 C104.1 C105.1 C106.1 C107.1 C108.1 C109.1 C111.1 C112.1 C113.1 C114.1 C115.1 C116.1 R109.1 U11.AA8(VDDC) U11.AA11(VDDC) U11.AA14(VDDC) U11.AA17(VDDC) U11.AA20(VDDC) U11.F7(VDDC) U11.F10(VDDC) U11.F13(VDDC) U11.F16(VDDC) U11.F19(VDDC) U11.G21(VDDC) U11.H6(VDDC) U11.K21(VDDC) U11.L6(VDDC) U11.L11(VDDC) U11.L16(VDDC) U11.N21(VDDC) U11.P6(VDDC) U11.T11(VDDC) U11.T16(VDDC) U11.T21(VDDC) U11.U6(VDDC) U11.W21(VDDC) U11.Y6(VDDC) ; also on sheet 5
P3P3V: C4.1 C11.1 C14.1 C21.1 C22.1 C24.1 C77.1 C147.1 C148.1 C149.1 C150.1 C151.1 C152.1 C153.1 C154.1 C155.1 C156.1 C157.1 C158.1 C159.1 F1.1 FB2.1 FB6.1 J6.1 R10.1 R17.2 R19.1 R28.1 R29.1 R30.1 R35.1 R50.1 R52.2 R53.1 R55.1 R56.1 R61.2 U6.2(VREF1) U9.8(VCC) U10.8(VCC) U11.AA7(VDD33) U11.AA10(VDD33) U11.AA16(VDD33) U11.AA19(VDD33) U11.AE26(CFO_VDD33) U11.F8(VDD33) U11.F11(VDD33) U11.F17(VDD33) U11.F20(VDD33) U11.L21(VDD33) U11.R21(VDD33) U11.Y21(VDD33) U12.5(VCC) ; also on sheet 4 5 6 7 8 9 10 11
PLLD_VAD_M1P8: C145.1 FB16.2 U11.K25(PLLD_VAD)
PLLD_VDD_M1P1: C135.1 FB15.2 U11.L22(PLLD_VDD)
PLLM1_VAD_M1P8: C110.1 FB12.2 U11.L24(PLLM1_VAD)
PLLM1_VDD_M1P1: C146.1 FB17.2 U11.L26(PLLM1_VDD)
PLLM2_VAD_M1P8: C133.1 FB14.2 U11.R25(PLLM2_VAD)
PLLM2_VDD_M1P1: C119.1 FB13.2 U11.P23(PLLM2_VDD)
PLLS_VAD_M1P1: C102.1 FB11.2 U11.R23(PLLS_VAD)
POWERGOOD: U11.T26(PWRGOOD) ; also on sheet 8 10
QA_B0: RP8.2 U8.10(QA2)
QA_B1: RP8.1 U8.13(QA3)
QA_B2: RP7.4 U8.14(QA4)
QA_B3: RP7.3 U8.15(QA5)
QA_B4: RP7.2 U8.16(QA6)
QA_B5: RP7.1 U8.17(QA7)
QA_B6: RP6.4 U8.18(QA8)
QA_B7: RP6.3 U8.19(QA9)
QA_B8: RP6.2 U8.22(QA10)
QA_B9: RP6.1 U8.23(QA11)
QA_G0: RP5.4 U8.26(QA14)
QA_G1: RP5.3 U8.27(QA15)
QA_G2: RP5.2 U8.28(QA16)
QA_G3: RP5.1 U8.29(QA17)
QA_G4: RP4.4 U8.30(QA18)
QA_G5: RP4.3 U8.31(QA19)
QA_G6: RP4.2 U8.32(QA20)
QA_G7: RP4.1 U8.33(QA21)
QA_G8: RP3.4 U8.34(QA22)
QA_G9: RP3.3 U8.35(QA23)
QA_R0: RP3.2 U8.42(QA26)
QA_R1: RP3.1 U8.43(QA27)
QA_R2: RP2.4 U8.44(QA28)
QA_R3: RP2.3 U8.45(QA29)
QA_R4: RP2.2 U8.46(QA30)
QA_R5: RP2.1 U8.47(QA31)
QA_R6: RP1.4 U8.48(QA32)
QA_R7: RP1.3 U8.50(QA33)
QA_R8: RP1.2 U8.51(QA34)
QA_R9: RP1.1 U8.52(QA35)
QB_B0: R34.1 U8.141(QB2)
QB_B1: R33.1 U8.142(QB3)
QB_B2: RP15.4 U8.143(QB4)
QB_B3: RP15.3 U8.144(QB5)
QB_B4: RP15.2 U8.145(QB6)
QB_B5: RP15.1 U8.146(QB7)
QB_B6: RP14.4 U8.151(QB8)
QB_B7: RP14.3 U8.152(QB9)
QB_B8: RP14.2 U8.153(QB10)
QB_B9: RP14.1 U8.154(QB11)
QB_G0: RP13.4 U8.155(QB14)
QB_G1: RP13.3 U8.156(QB15)
QB_G2: RP13.2 U8.157(QB16)
QB_G3: RP13.1 U8.158(QB17)
QB_G4: RP12.4 U8.159(QB18)
QB_G5: RP12.3 U8.160(QB19)
QB_G6: RP12.2 U8.161(QB20)
QB_G7: RP12.1 U8.164(QB21)
QB_G8: RP11.4 U8.165(QB22)
QB_G9: RP11.3 U8.166(QB23)
QB_R0: RP11.2 U8.167(QB26)
QB_R1: RP11.1 U8.168(QB27)
QB_R2: RP10.4 U8.169(QB28)
QB_R3: RP10.3 U8.170(QB29)
QB_R4: RP10.2 U8.171(QB30)
QB_R5: RP10.1 U8.172(QB31)
QB_R6: RP9.4 U8.173(QB32)
QB_R7: RP9.3 U8.174(QB33)
QB_R8: RP9.2 U8.175(QB34)
QB_R9: RP9.1 U8.176(QB35)
SSP0_CLK: R57.2 ; also on sheet 6
SSP0_CSZ0_DAD1: R59.2 ; also on sheet 6
SSP0_CSZ1_DMD: R58.2 ; also on sheet 6
SSP0_RXD_S2M: R56.2 U11.AD5(SSP0_RXD) ; also on sheet 6
SSP0_TXD_M2S: R54.2 ; also on sheet 6
TRIGGER_IN1: U11.AF7(TRIG_IN_1) ; also on sheet 7
USB_DAT_N: J7.2 R63.1 U13.3(NC3) U13.4(B)
USB_DAT_P: J7.3 R62.2 R64.1 U13.1(NC1) U13.6(A)
USB_SENSE: R62.1 TP16.1 U12.4(Y)
USB_VBUS: J7.1 R60.1 U12.2(A)
XTAL_N: C76.1 R48.1 X2.1
N20158334: R5.2 R9.1 U5.1(E0)
N20187524: TP3.1 U8.134(SCK_DCLK_MCLK)
N20187527: TP2.1 U8.135(WS_DR0)
N20187534: TP4.1 U8.136(I2S0_DL0)
N20187537: TP5.1 U8.137(I2S1_DR1)
N20187540: TP6.1 U8.138(I2S2_DL1)
N20187543: TP7.1 U8.139(I2S3_DR2)
N20187546: TP8.1 U8.140(SPDIF_DL2)

Not connected (* = marked no-connect by the designer): J1 13(CE_Remote)* 14(NC)*; U7 1; U8 8(QA0)* 9(QA1)* 24(QA12)* 25(QA13)* 40(QA24)* 41(QA25)* 53(NC)* 54(NC)* 55(NC)* 56(NC)* 57(NC)* 58(NC)* 59(NC)* 60(NC)* 61(NC)* 62(NC)* 63(NC)* 64(NC)* 65(NC)* 66(NC)*; U11 AB4(RESERVED)* AB10(RESERVED)* AC3(SSP0_CSZ_2)* AD9(RESERVED)* AD11(RESERVED)* AD12(RESERVED)* AE9(RESERVED)* AE11(RESERVED)* AF11(RESERVED)* AF23(P_CLK3)* B23(RESERVED)* C22(RESERVED)* D25(RESERVED)* D26(RESERVED)* E24(RESERVED)* F22(RESERVED)* F23(RESERVED)* F25(RESERVED)* T25(CTRL_ARSTZ)*; X1 2* 4*

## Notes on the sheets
sheet 12
- UART debug message port,
  not needed for production
- Buffer to prevent host from detecting
  the USB slave before ARM finishes
  initialization
- Controller SSP0, UART0, USB, Reset, OSC
sheet 13
- Swap A/B channel, and buses' bit order for
  ease of routing to flex connector
- Note: RC Filtering required only for
  TI reference design's flex cable
  due to impedance mismatch
- Controller Video Input, DMD & DAD Output
sheet 14
- COMPUTER GENERATED DRAWING - DO NOT REVISE MANUALLY
- NOTES, UNLESS OTHERWISE SPECIFIED:
- REVISIONS
- REV
- DESCRIPTION
- DATE
- APPROVED
- 1.
- The netname "P12V" represents connection to the +12V power plane.
- A
- ECO 2139077: Initial Release
- 2/18/2014
- 2.
- The netname "P3P3V" represents connection to the +3.3V power plane.
- 3.
- The netname "P1P8V" represents connection to the +1.8V digital power plane.
- B
- ECO 2141121: Updated to rev B
- 4/8/2014
- C
- ECO 2142182: Updated to rev C
- 4.
- The netname "P1P15V" represents connection to the +1.15V  power plane.
- 5/28/2014
- D
- ECO 2143315: Updated to rev D
- 8/11/2014
- 5.
- The netname "P1P8V_A" represents connection to the +1.8V controller analog supply power plane.
- 6.
- The netname "GND" represents connection to the ground plane.
- 7.
- A "Z" suffix on a signal name indicates an active low signal.
- 8.
- All components with designators "U*", "Q*", and "D*" are electrostatic discharge sensitive.
- xxxxxxxx
- 0314PO
sheet 15
- Table of Contents
- Page
- Description
- 1
- Title
- 2
- Import Notice for TI Products
- 3
- Table Of Contents
- 4
- Block Diagram
- 5
- HDMI, DisplayPort Input/ESD
- 6
- IT6535 Input/Ouput Ports
- 7
- IT6535 Power/Ground Bypass
- 8
- DLPC Controller Video, DMD, DAD in/out ports
- 9
- DLPC Controller: USB, Reset/Clock, SSP0
- 10
- DLPC Controller: 128Mb x 3 flash interface
- 11
- DLPC Controller: JTAG, ICE interface
- 12
- DLPC Controller: I2C, Dual Controller ports, Trigger GPIOs
- 13
- DLPC Controller: Power/Ground Bypass
- 14
- DMD Flex Connector
- 15
- Power Conv: 12V -->1.15V, 1.8V, 3.3V switchers
- 16
- Power Conv: LDOs
- 17
- Input/output triggers, LED driver connector
- 18
- Posense, Powergood
- 19
- Notes & Revision History
sheet 16
- I2C Ext
  Connector
  Page 12
- LED driver
  Conn
  Page 17
- Ext. Parallel
  Flash
  Page 10
- Ex Trigger
  Conn
  Page 17
- USB Jack &
  ESD Protection
  Page 9
- LED driver
  GPIO
  Page 12
- Ext Memory
  Interface
  Page 10
- Ext Trigger
  Interface
  Page 12
- I2C
  Page 12
- 3.3V
- Pwr/Gnd
  Bypass
  Page 13
- USB
  Page 9
- DisplayPort
  EDID
  Page 6
- HDMI EDID
  Page 5
- HDMI Type A
  Connector
  Page 5
- Odd/Even
  Pixel Input
  Page 8
- DLPC900
- DMD LVDS
  Data Out
  Page 8
- HDMI Receiver
  IT6535
  Page 6, 7
- DMD Flex
  Connection
  Page 14
- ESD
  Protection
  Page 5
- DisplayPort
  Connector
  Page 5
- Master
  Strap Pin
  Page 12
- DAD
  Control
  Page 8
- Ext. Parallel
  Source Conn.
  Page 20
- Powergood,
  Reset, Clk In
  Page 9
- SCP (SSP0)
  Interface
  Page 9
- ARM uP ICE
  Page 11
- DSTREAM Prog.
  Page 11
- 20MHz Xtal
  Page 9
- 3.3V to 1.8V
  HDMI Rx Analog
- 12V Input
  Page 15
- 12V to 3.3V
- POSENSE &
  PWRGOOD
  Generation
  Page 18
- 3.3V to 1.8V
  Controller
  Analog
- 12V Monitor
- 12V to 1.15V
  Controller
  Core
- 1.15V DLPC Controller Core
  1.8V digital
  1.8V DLPC Controller Analog
  1.8V HDMI Rx Analog
  3.3V HDMI, Controller IO power
- 12V to 1.8V
- Power Conversion
  Page 15, 16
sheet 17
- Apply a crystal input
  even audio function
  is not used per ITE
  recommandation
- Must connect I2C and interrupt
  to controller for register setup
- I2C address select
  low = 0xB0
  high = 0xB2
- HDMI receiver input/output
sheet 18
- Controller Pwr Gnd
sheet 19
- 3.3V IO
- Digital logic core
- DP analog frontend
- Logic power for analog frontend
- 3.3V HDMI RX analog frontend
- 1.8V HDMI RX analog frontend
- DP Rx PLL power
- Crystal and audio PLL
- HDMI Rx PLL power
- HDMI receiver power/gnd bypass
sheet 20
- To program HDMI EDID
  - install jumper to enable PROM write and disable hot plug detect
  - connect HDMI cable to supply 5V
  - use TI control program to update EDID
- HDMI TypeA Rx Conn, ESD, and EDID
- DisplayPort Rx Conn, ESD
